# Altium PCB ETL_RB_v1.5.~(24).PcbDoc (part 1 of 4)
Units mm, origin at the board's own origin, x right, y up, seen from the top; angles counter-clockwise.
Board outline 130.3 x 56.5 mm, 8 copper layers (Top Layer, plane 1, M1, plane 2, plane 3, M2, plane 4, Bottom Layer), stack 0.972 mm thick; 212 components, 186 nets, 1961 pads, 978 vias.
Unrouted connection lines stored in the file: 395.
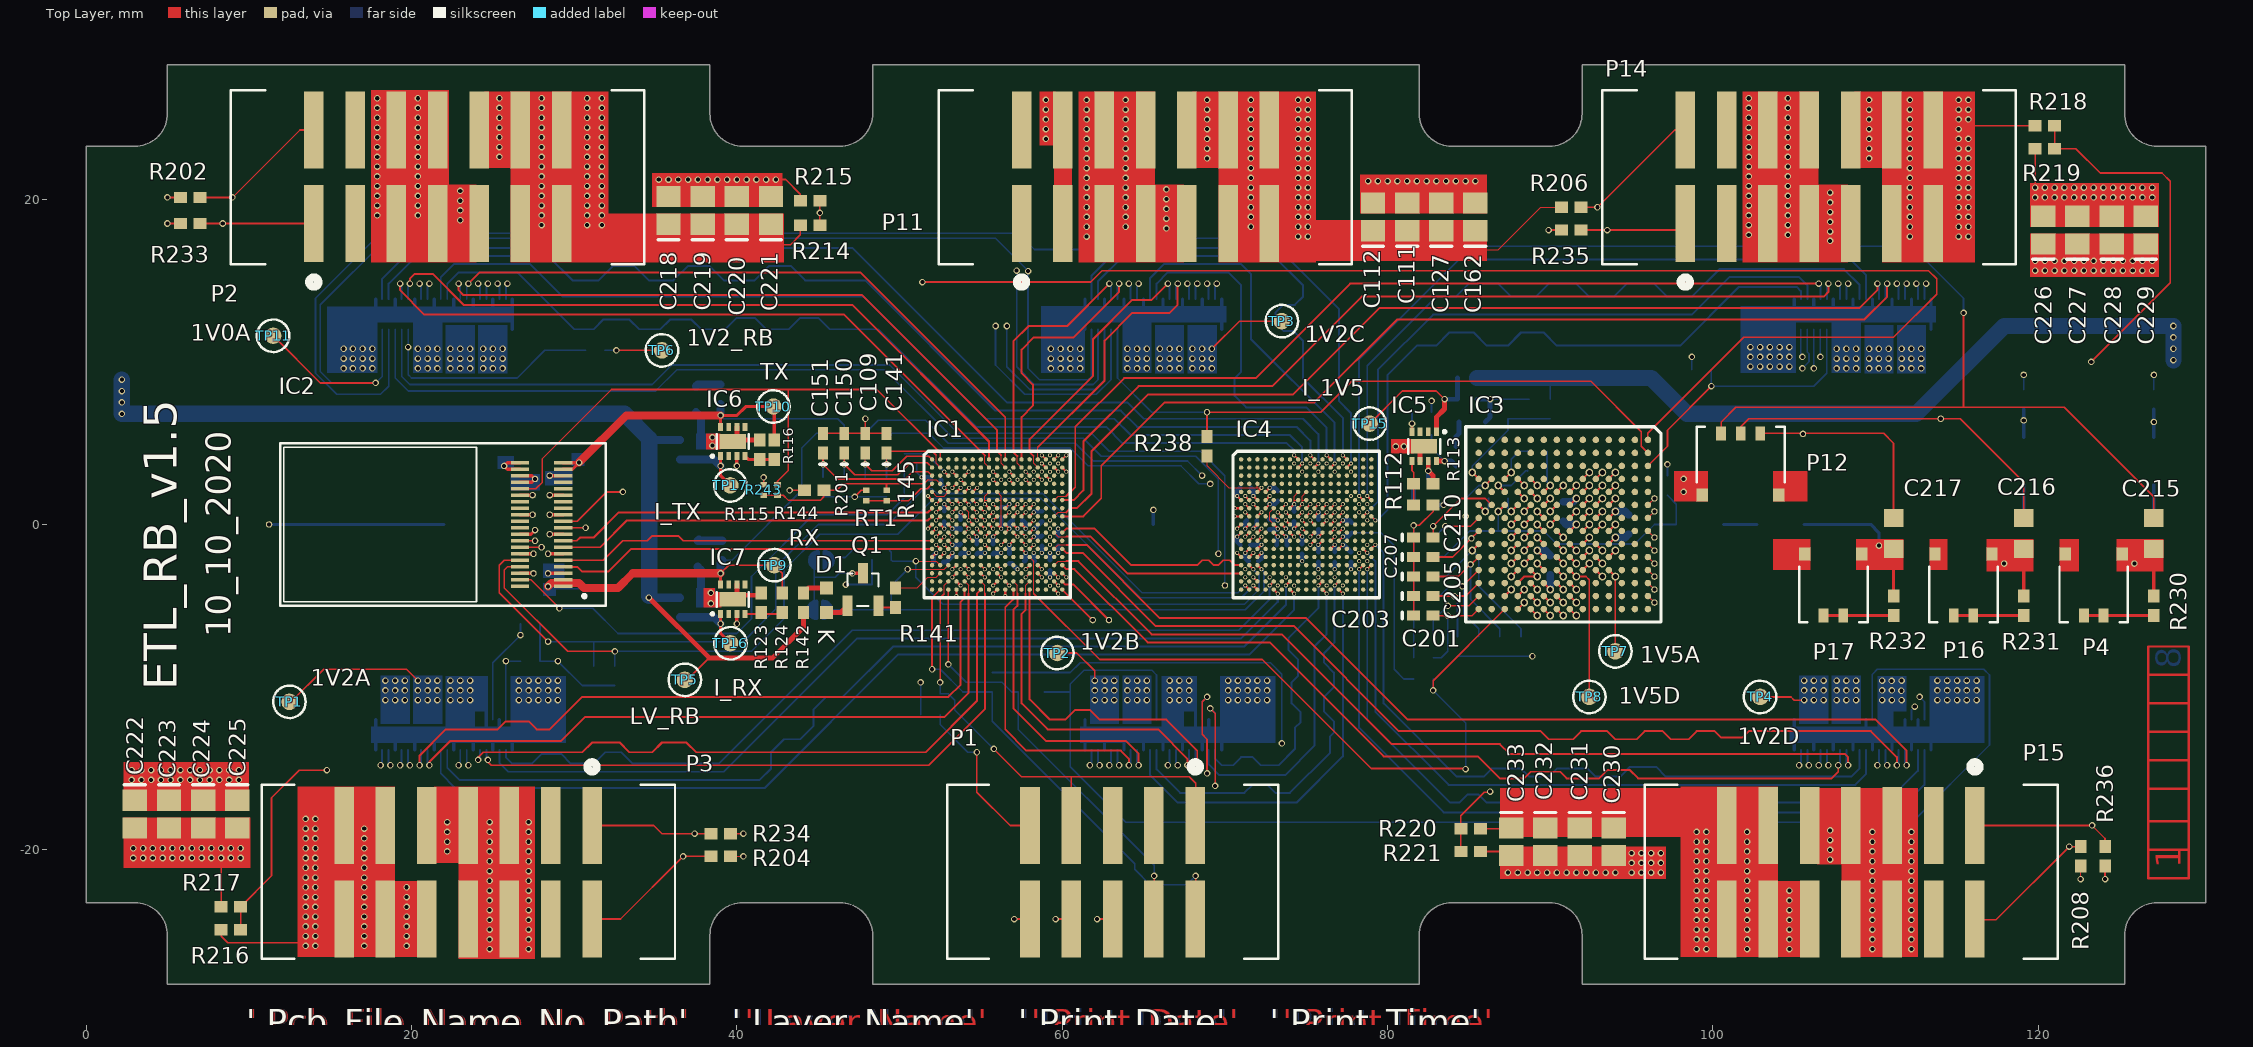
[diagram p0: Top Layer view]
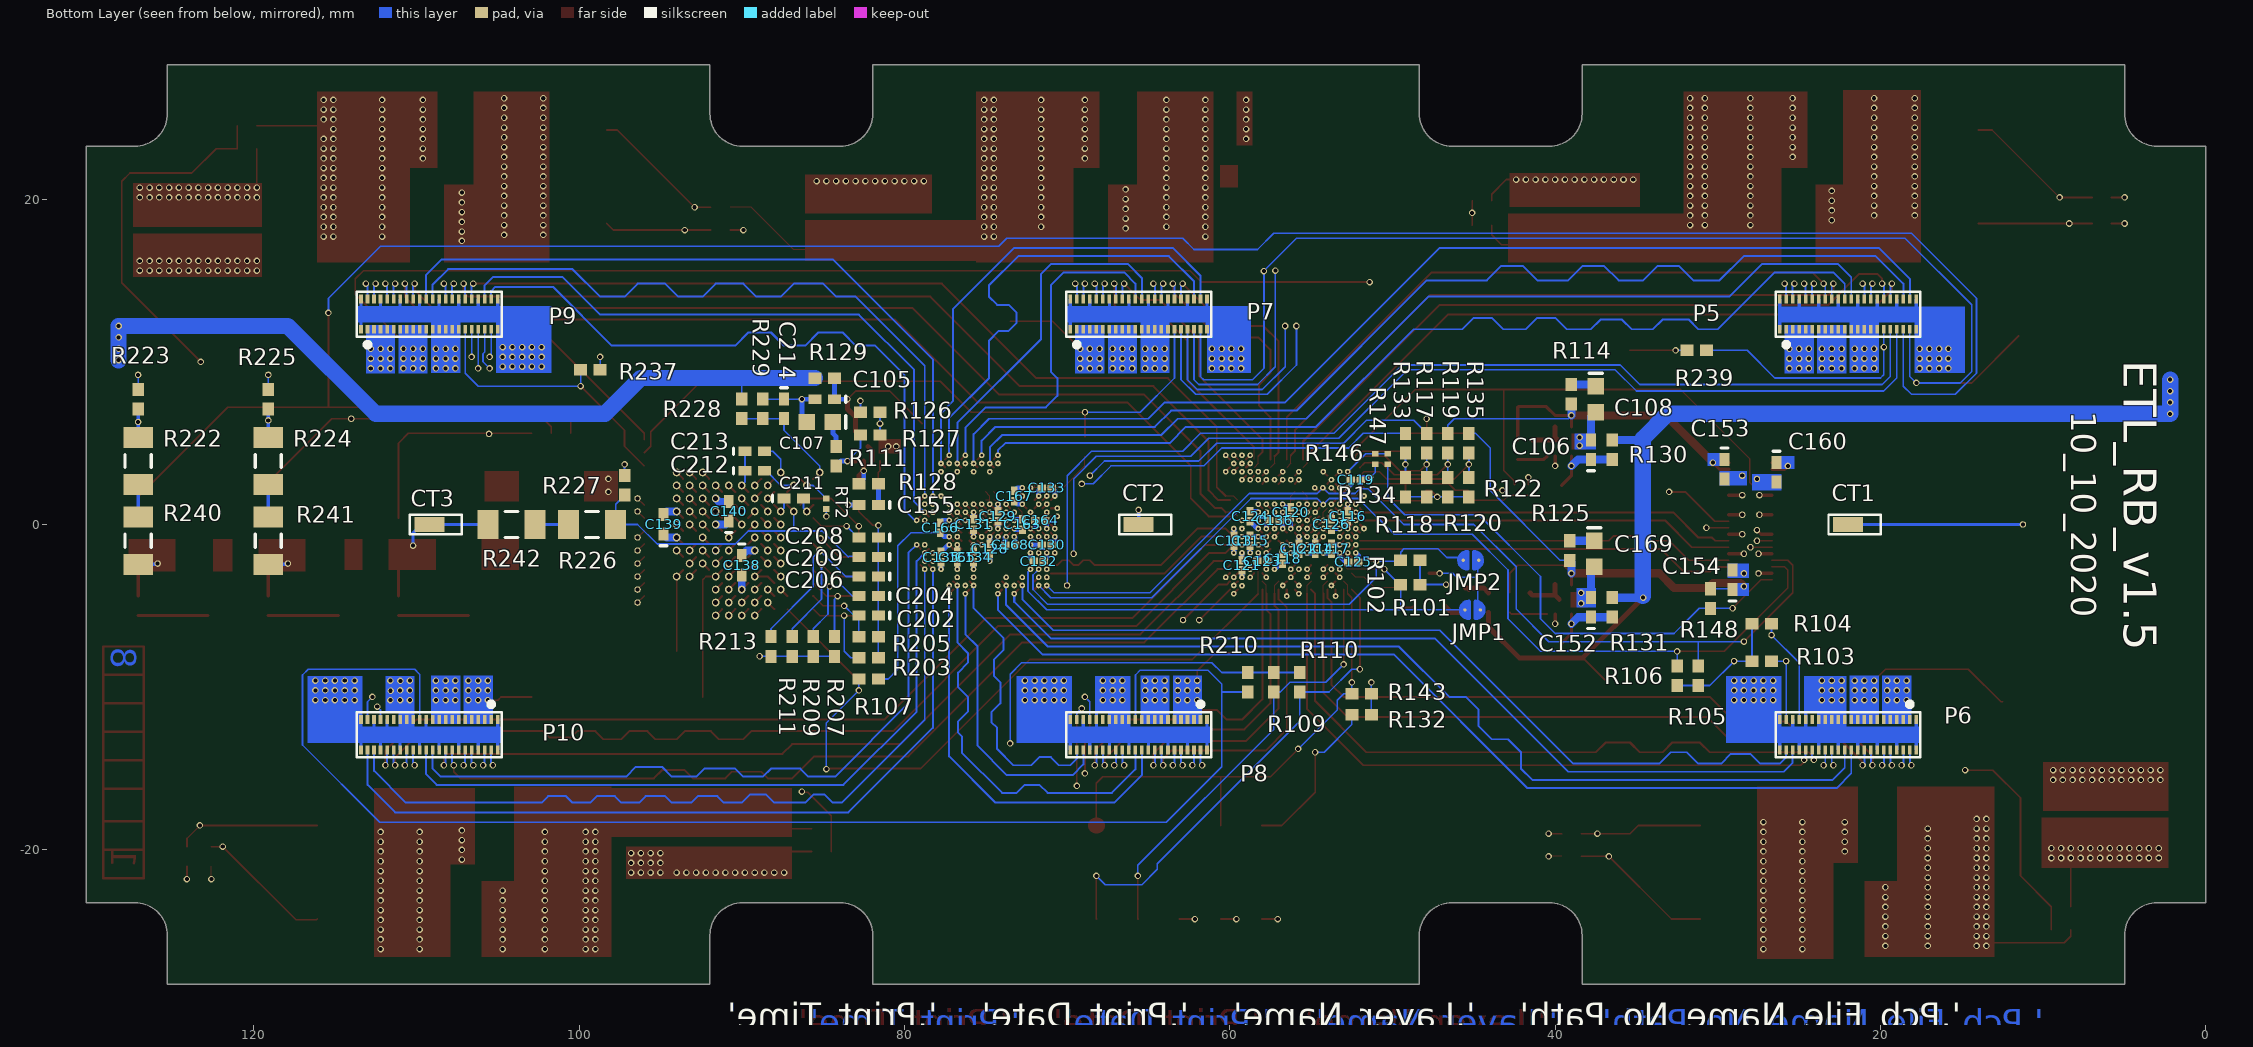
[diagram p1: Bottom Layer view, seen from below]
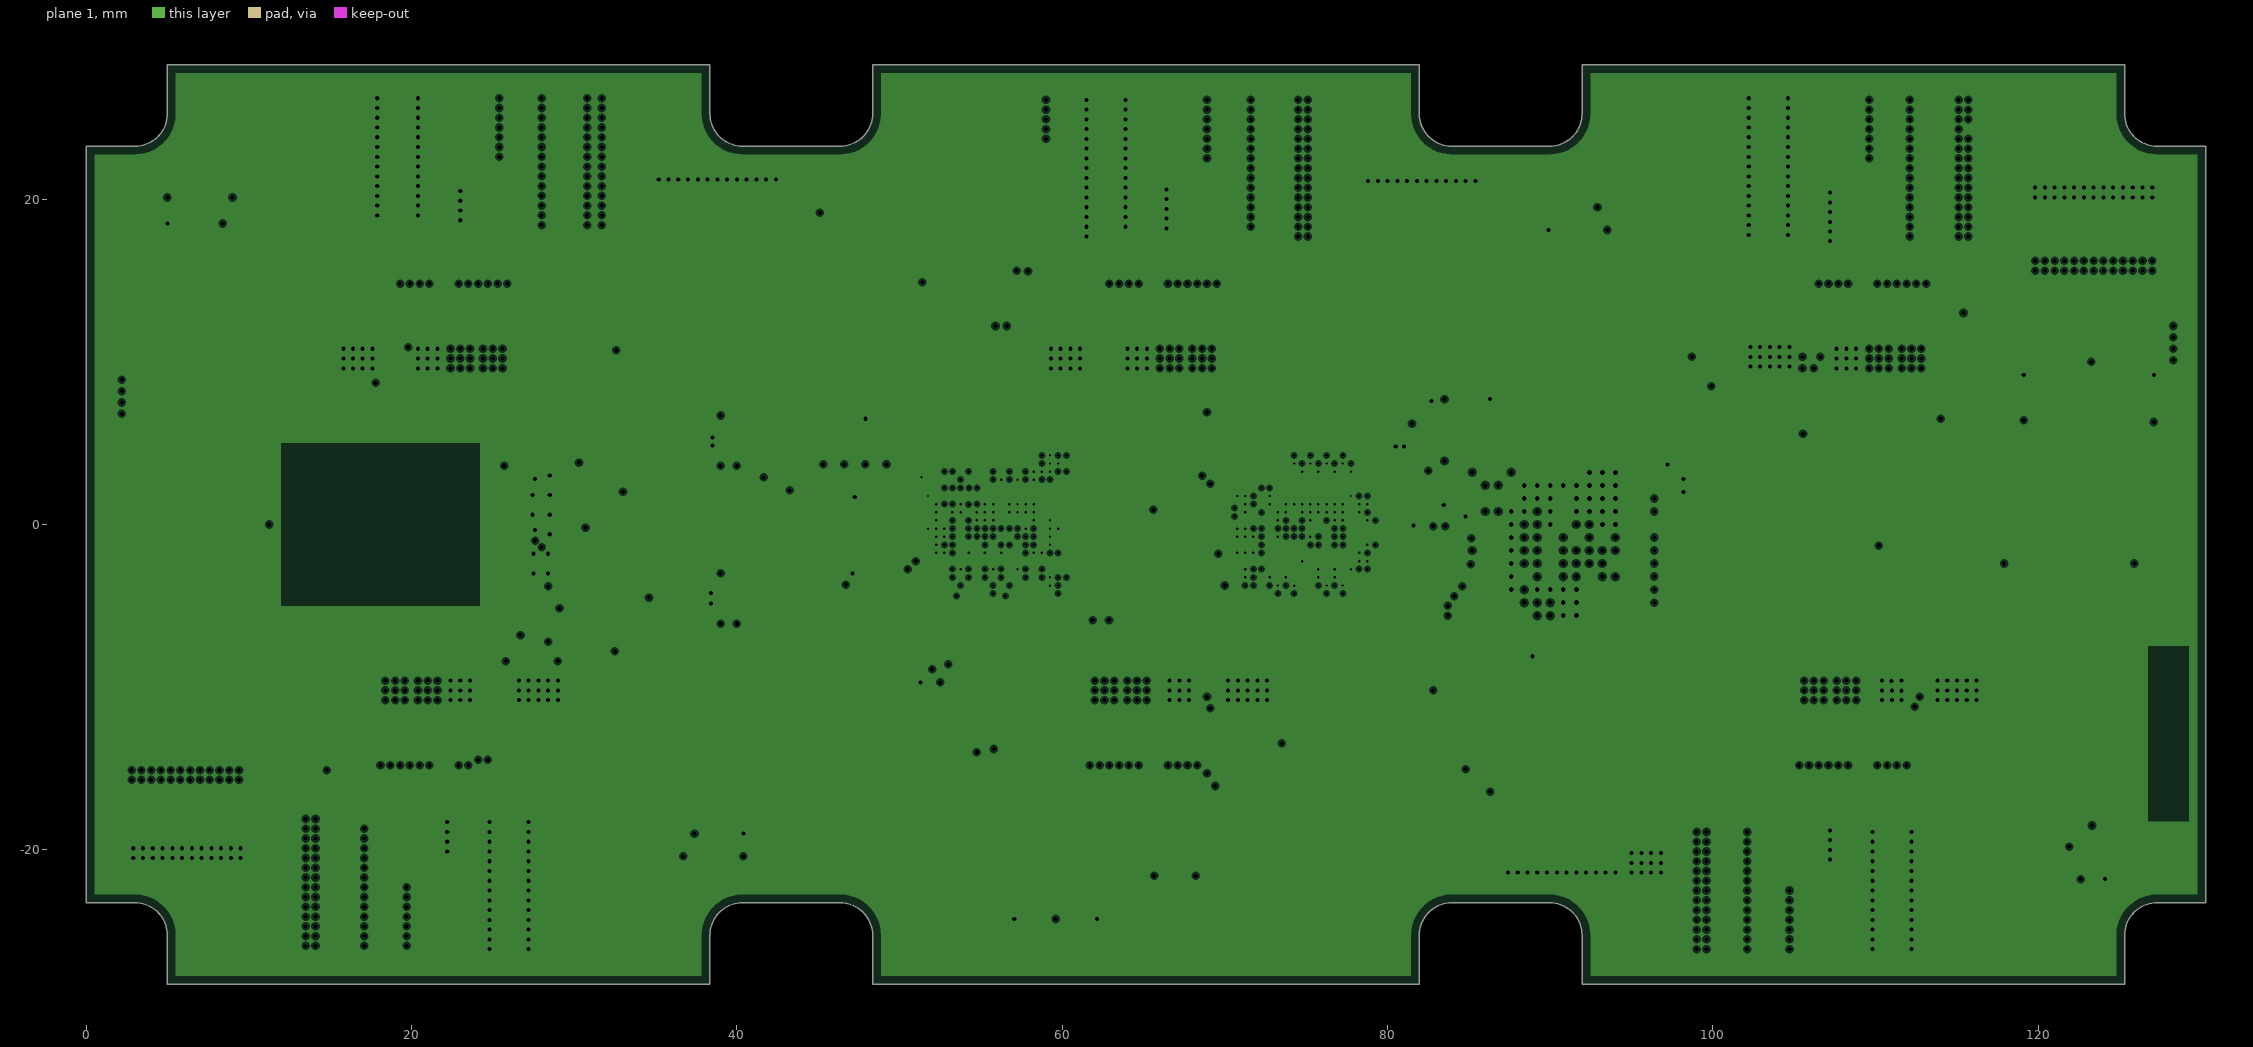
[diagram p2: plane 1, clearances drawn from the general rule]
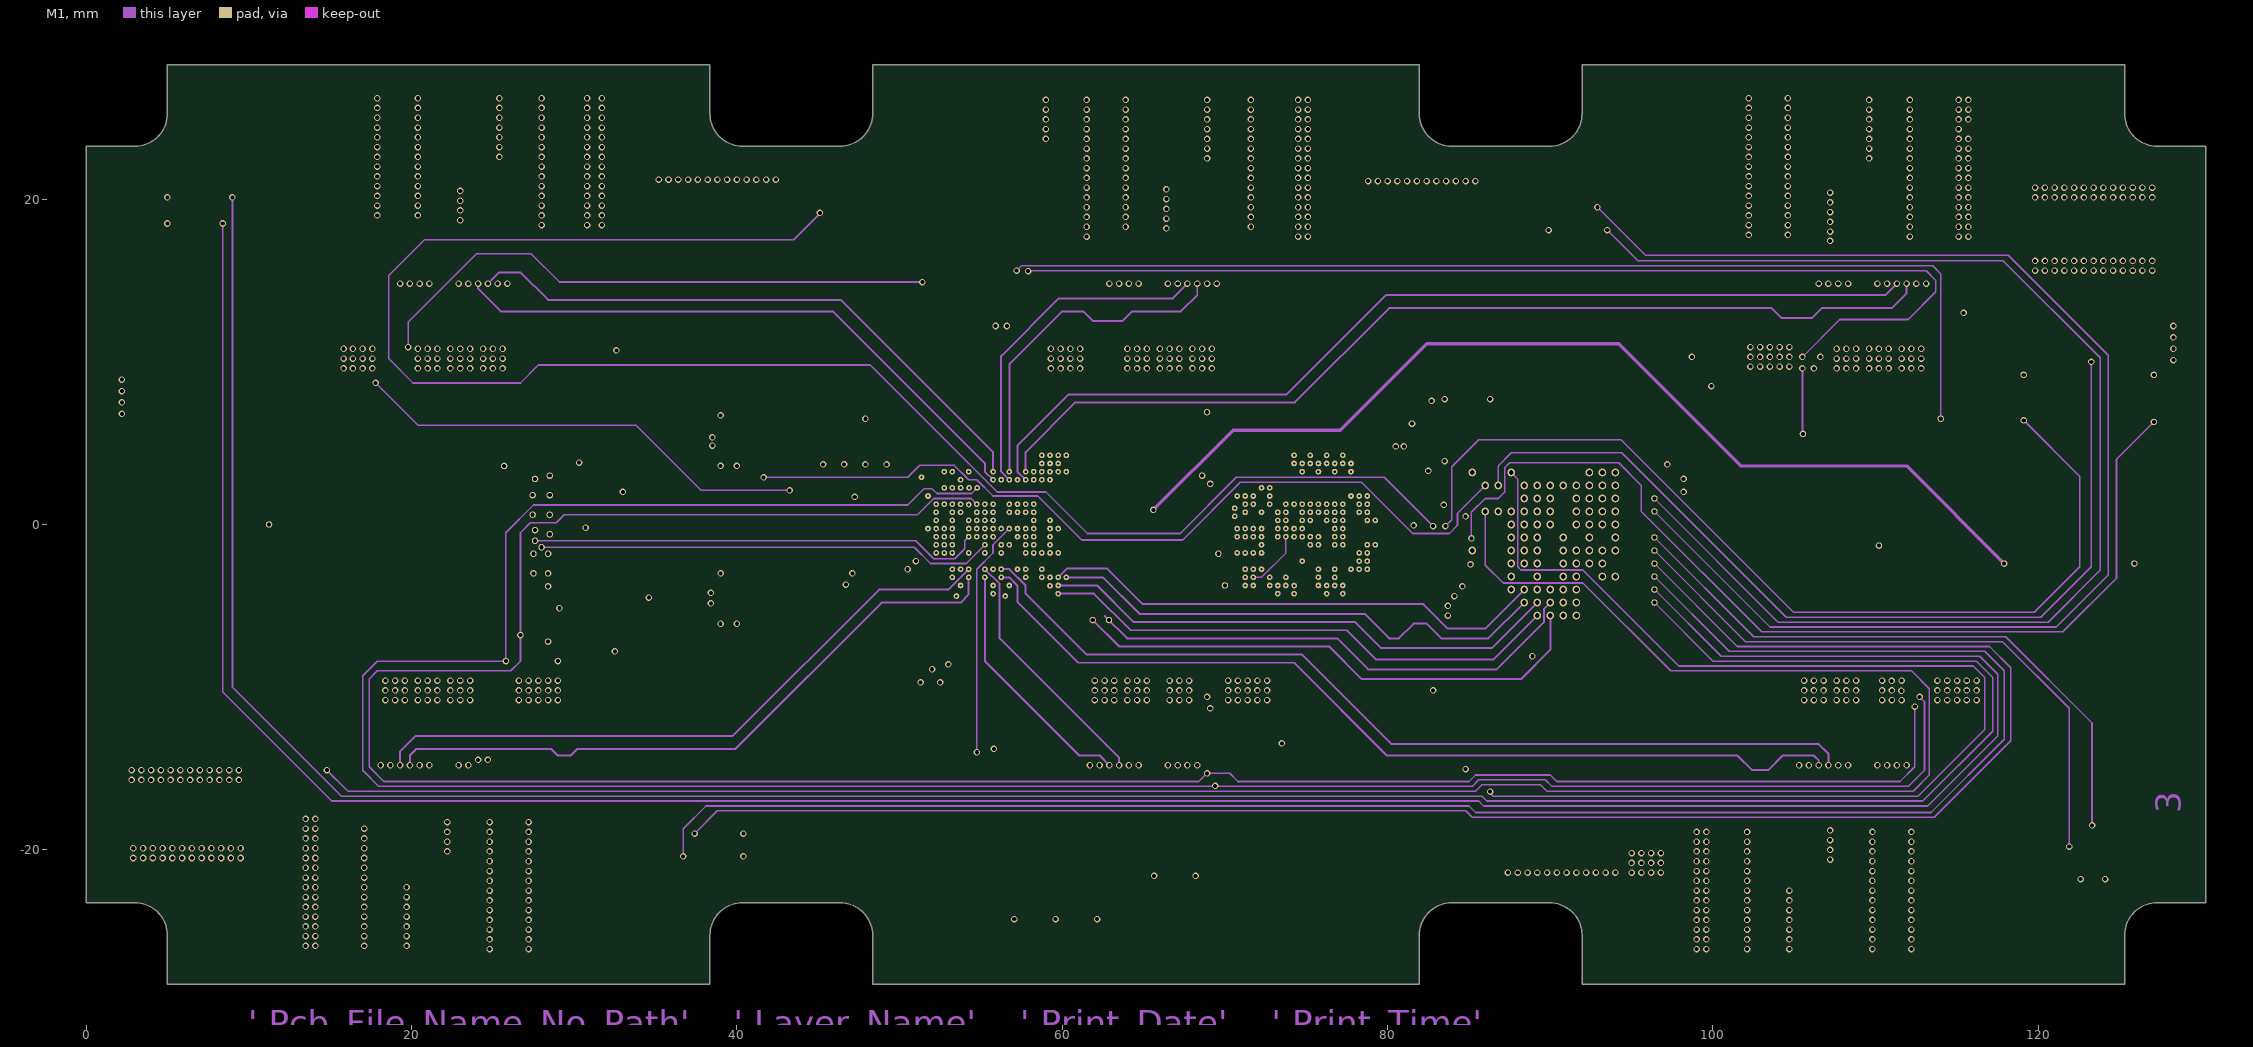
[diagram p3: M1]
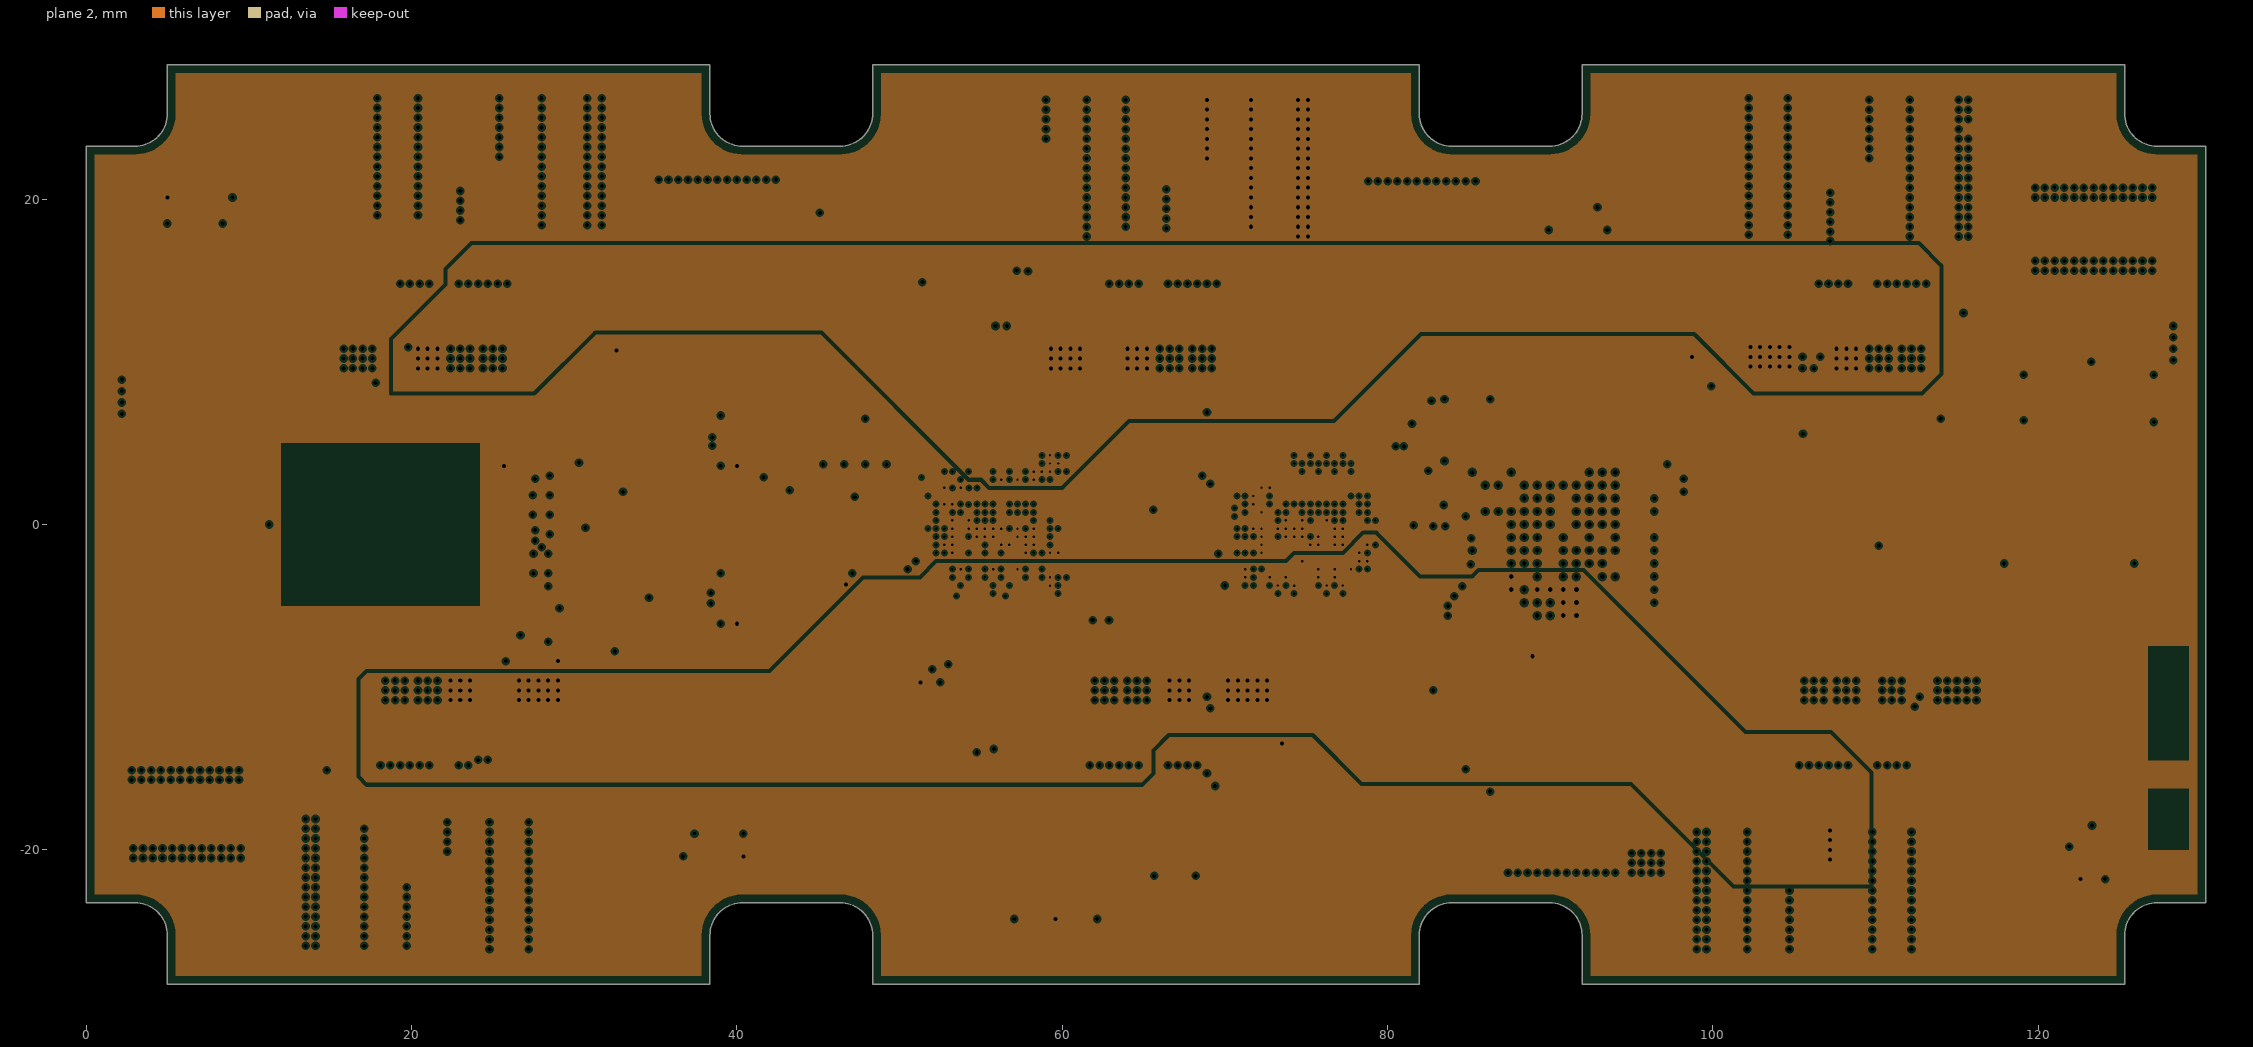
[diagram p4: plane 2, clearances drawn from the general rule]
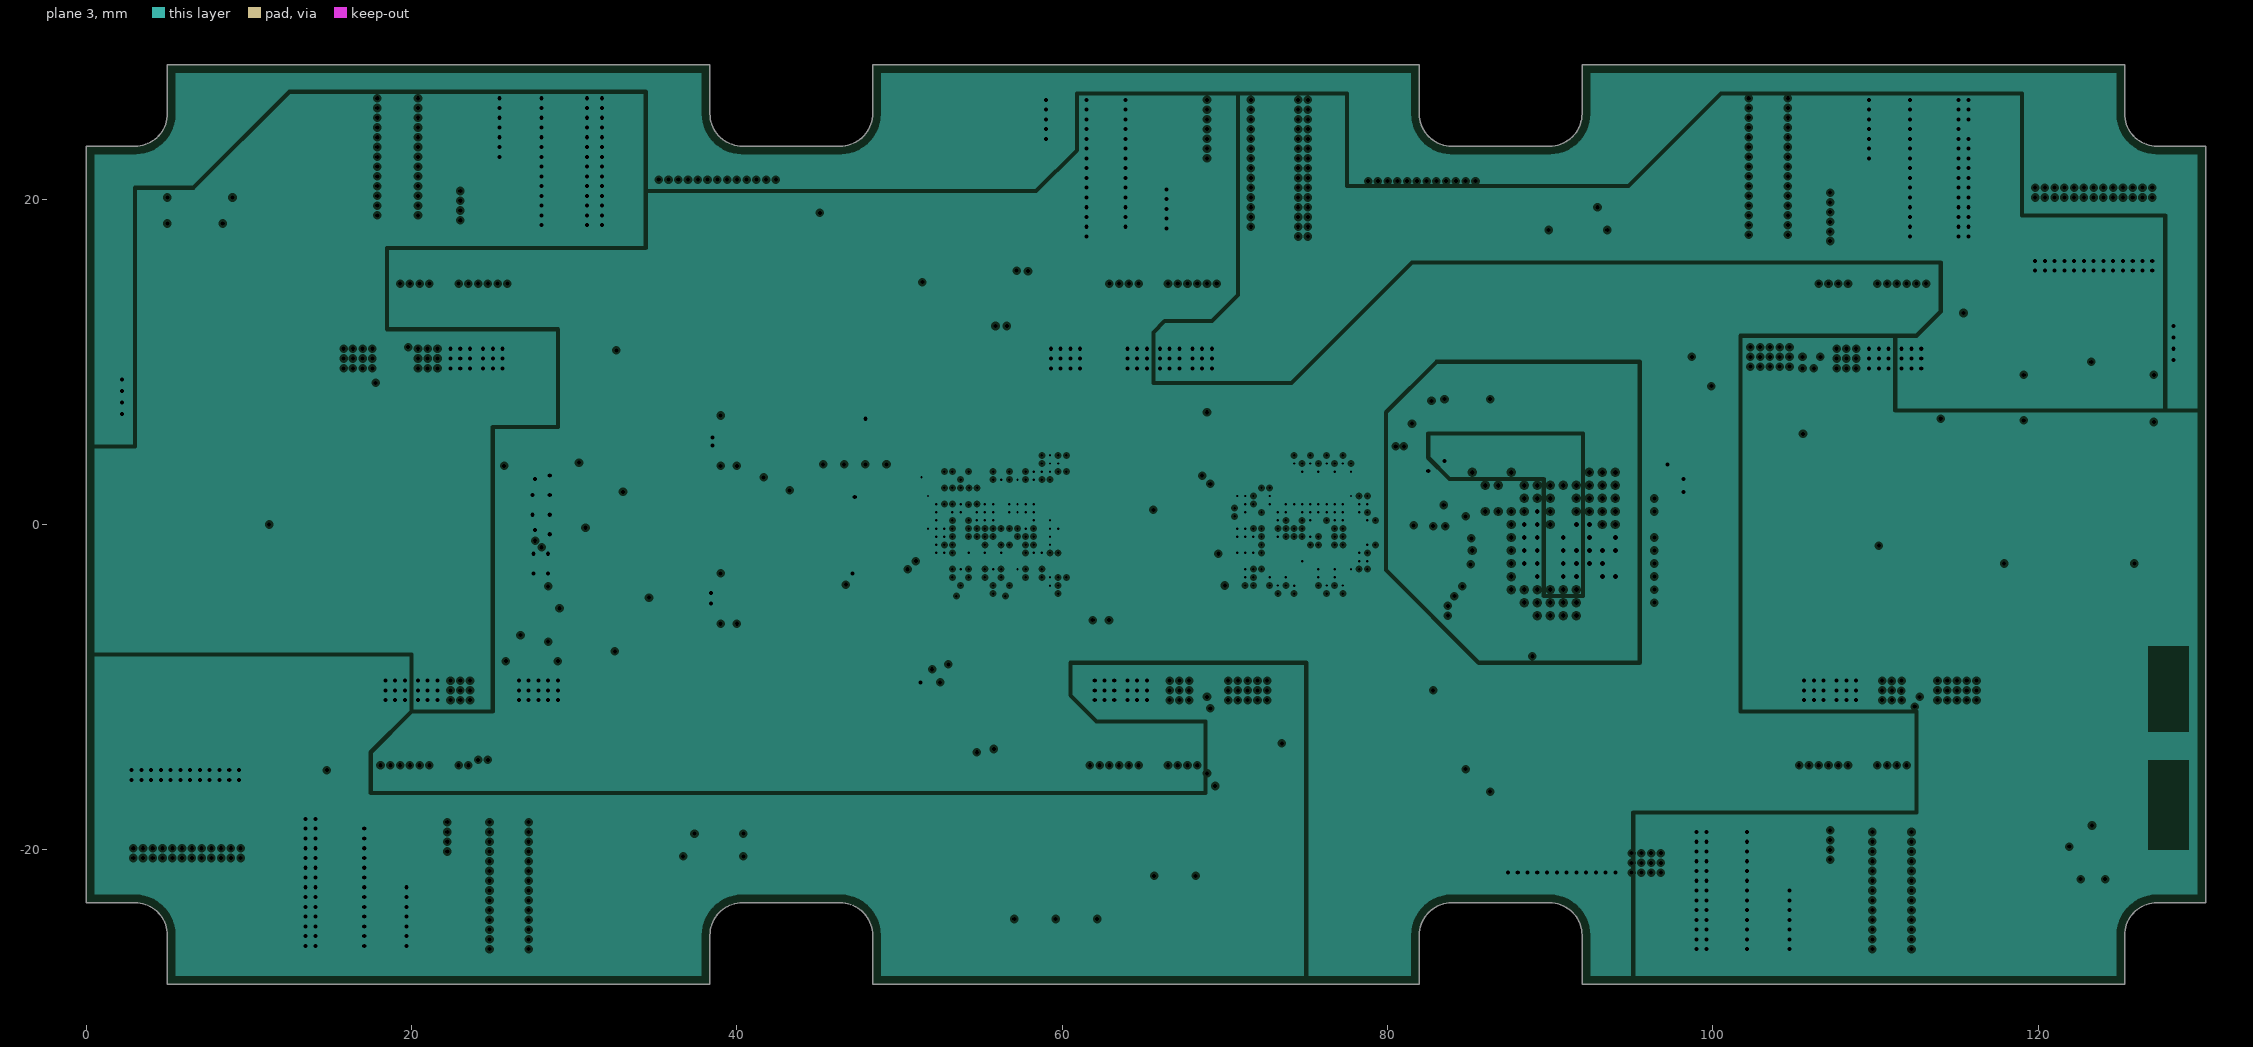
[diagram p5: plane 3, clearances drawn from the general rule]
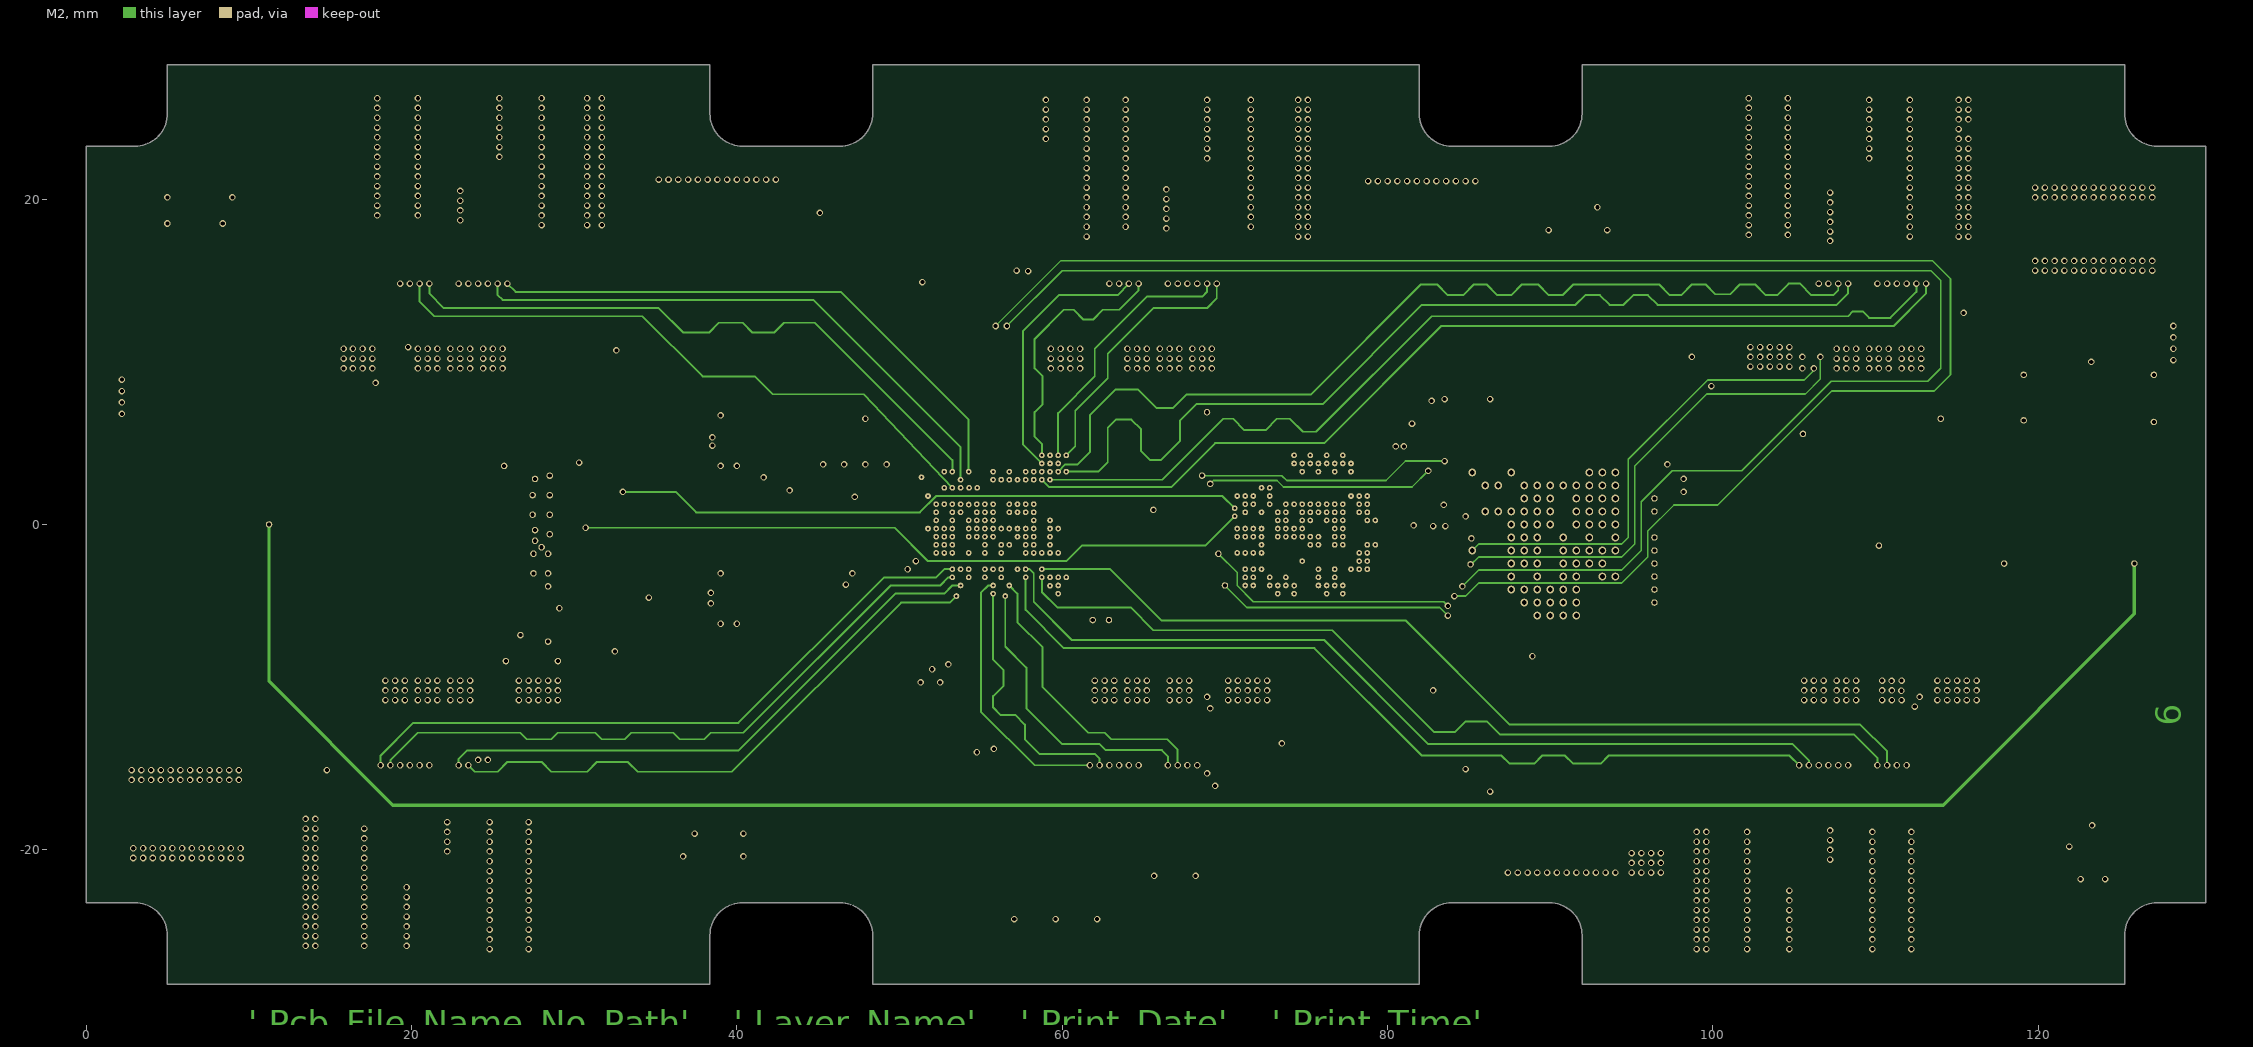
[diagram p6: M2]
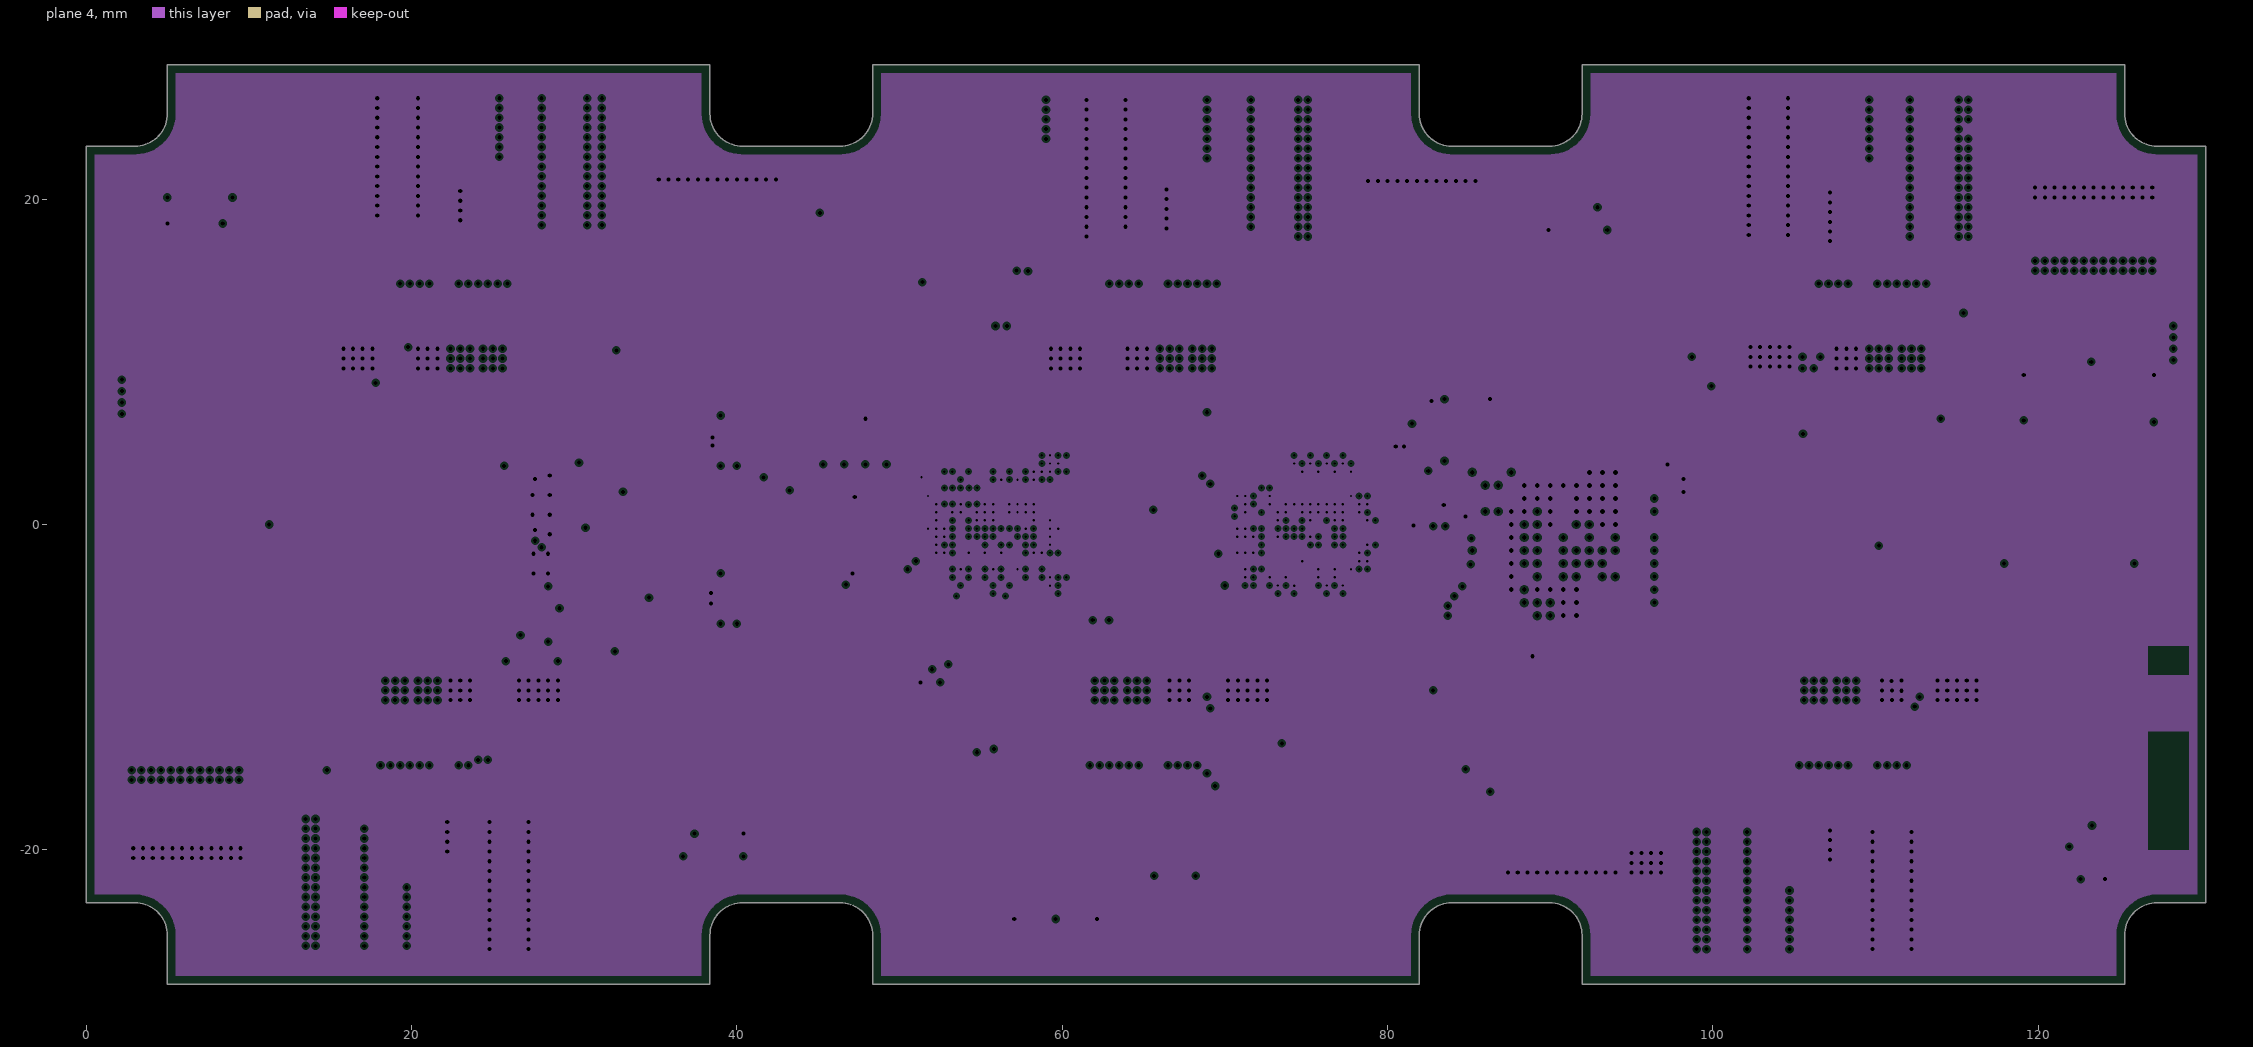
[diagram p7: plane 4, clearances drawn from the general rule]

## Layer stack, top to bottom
Top Solder: solder mask 0.0178, Solder Resist, Dk 4.1
Top Layer: signal copper 0.035
Dielectric 1: prepreg 0.0691, 1080, Dk 3.4
plane 1: plane copper 0.035, net GND
Dielectric 2: core 0.1016, TU-863, Dk 3.7
M1: signal copper 0.018
Dielectric 3: prepreg 0.1417, 1080, Dk 3.4
plane 2: plane copper 0.035, net (Multiple Nets)
Dielectric 4: core 0.1016, TU-863, Dk 3.7
plane 3: plane copper 0.035, net (Multiple Nets)
Dielectric 5: prepreg 0.1417, 1080, Dk 3.4
M2: signal copper 0.018
Dielectric 6: core 0.1016, TU-863, Dk 3.7
plane 4: plane copper 0.035, net GND
Dielectric 7: prepreg 0.0691, 1080, Dk 3.4
Bottom Layer: signal copper 0.035
Bottom Solder: solder mask 0.0178, Solder Resist, Dk 4.1

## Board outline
5,-28.25 5,-25.25 ccw(c3,-25.25) 3,-23.25 0,-23.25 0,23.25 3,23.25 ccw(c3,25.25) 5,25.25 5,28.25 38.35,28.25 38.35,25.25 ccw(c40.35,25.25) 40.35,23.25 46.35,23.25 ccw(c46.35,25.25) 48.35,25.25 48.35,28.25 81.95,28.25 81.95,25.25 ccw(c83.95,25.25) 83.95,23.25 89.95,23.25 ccw(c89.95,25.25) 91.95,25.25 91.95,28.25 125.3,28.25 125.3,25.25 ccw(c127.3,25.25) 127.3,23.25 130.3,23.25 130.3,-23.25 127.3,-23.25 ccw(c127.3,-25.25) 125.3,-25.25 125.3,-28.25 91.95,-28.25 91.95,-25.25 ccw(c89.95,-25.25) 89.95,-23.25 83.95,-23.25 ccw(c83.95,-25.25) 81.95,-25.25 81.95,-28.25 48.35,-28.25 48.35,-25.25 ccw(c46.35,-25.25) 46.35,-23.25 40.35,-23.25 ccw(c40.35,-25.25) 38.35,-25.25 38.35,-28.25

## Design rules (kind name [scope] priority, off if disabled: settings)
Clearance [All] p1: gap=0.076 ignorepadtopadclearanceinfootprint=FALSE except(0: Arc-Hole Track-Hole SMDPad-Hole THPad-Hole Via-Hole Fill-Hole Poly-Hole Region-Hole Text-Hole)
Height [All] p1 off: minheight=0 maxheight=25.4 prefheight=12.7
HoleToHoleClearance HoleToHoleClearance_1 [InNet('GND') or InNet('LV_RB') or InNet('1V5A') or InNet('1V5D') or InNet('1V2A') or InNet('1V2B') or InNet('1V2C') or InNet('1V2D') vs InNet('GND') or InNet('LV_RB') or InNet('1V5A') or InNet('1V5D') or InNet('1V2A') or InNet('1V2B') or InNet('1V2C') or InNet('1V2D')] p1: gap=0.15 allowstackedmicrovias=TRUE
HoleToHoleClearance [All] p2: gap=0.254 allowstackedmicrovias=TRUE
MinimumSolderMaskSliver [All] p1: minsoldermaskwidth=0.025
PlaneClearance PlaneClearance_1 [InNetClass('BV')] p1: clearance=0.508
PlaneClearance [All] p2: clearance=0.14
PlaneConnect PlaneConnect_1 [All] p1: planeconnectstyle=Direct reliefexpansion=0.508 reliefentries=4 reliefconductorwidth=0.254 reliefairgap=0.254
PolygonConnect [All] p1: connectstyle=Relief reliefconductorwidth=0.254 reliefentries=4 polygonreliefangle="90 Angle" airgapwidth=0.254
RoomDefinition WP7B [InComponentClass('WP7B')] p1 off: confinementstyle=ConfineIn formatcopy=TRUE lockcomponents=FALSE outline 192.75,16.8 613.75,16.8 613.75,46.8 192.75,46.8
RoomDefinition lpGBT [InComponentClass('lpGBT')] p2 off: confinementstyle=ConfineIn formatcopy=TRUE lockcomponents=FALSE outline 192,-36.75 1047,-36.75 1047,-1.75 192,-1.75
RoutingVias [All] p1: holewidth=0.25 width=0.4 viastyle="Through Hole" minholewidth=0.15 minwidth=0.25 maxholewidth=0.711 maxwidth=1.27
SilkToSilkClearance [All] p1: silktosilkclearance=0.025
SilkToSolderMaskClearance [IsPad] p1: minsilkscreentomaskgap=0.025 clearancetoexposedcopper=TRUE
SolderMaskExpansion [All] p1: expansion=0.051 istentingtop=FALSE
Width Width_HS [InNetClass('HS')] p1: maxlimit=0.13 minlimit=0.076 preferedwidth=0.12 midlayer1_minwidth=0.12 midlayer1_maxwidth=0.12 midlayer2_minwidth=0.12 midlayer2_maxwidth=0.12 bottomlayer_minwidth=0.12 bottomlayer_maxwidth=0.12 minimp=50.000000 maximp=50.000000 favimp=50.000000 // impedance controlled signals
Width [All] p2: maxlimit=2.54 minlimit=0.076 preferedwidth=0.12 toplayer_minwidth=0.076 midlayer1_minwidth=0.076 minimp=50.000000 maximp=50.000000 favimp=50.000000
23 further rules are at their usual default settings.

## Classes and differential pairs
component class WP7B: C201 C202 C203 C204 C205 C206 C207 C208 C209 C210 C211 C212 C213 C214 C215 C216 C217 C218 C219 C220 C221 C222 C223 C224 C225 C226 C227 C228 C229 C230 C231 C232 C233 CT1 CT2 CT3 P2 P3 P4 P5 P6 P7 P8 P9 P10 P12 P14 P15 P16 P17 R201 R202 R203 R204 R205 R206 R207 R208 R209 R210 R211 R213 R214 R215 R216 R217 R218 R219 R220 R221 R222 R223 R224 R225 R226 R227 R228 R229 R230 R231 R232 R233 R234 R235 R236 R237 R238 R239 R240 R241 R242 R243 RT2 TP1 TP2 TP3 TP4 TP5 TP6 TP7 TP8 TP9 TP10 TP11
component class lpGBT: C105 C106 C107 C108 C109 C111 C112 C113 C114 C115 C116 C117 C118 C119 C120 C121 C122 C123 C124 C125 C126 C127 C128 C129 C130 C131 C132 C133 C134 C135 C136 C138 C139 C140 C141 C150 C151 C152 C153 C154 C155 C160 C162 C163 C164 C165 C166 C167 C168 C169 D1 IC1 IC2 IC3 IC4 IC5 IC6 IC7 JMP1 JMP2 P1 P11 Q1 R101 R102 R103 R104 R105 R106 R107 R109 R110 R111 R112 R113 R114 R115 R116 R117 R118 R119 R120 R122 R123 R124 R125 R126 R127 R128 R129 R130 R131 R132 R133 R134 R135 R141 R142 R143 R144 R145 R146 R147 R148 RT1 TP15 TP16 TP17

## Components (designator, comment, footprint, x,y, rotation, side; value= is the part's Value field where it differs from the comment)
C105 "GRM155R71E104ME14D" capc1005n 84.9,7.7 r0 bottom value=0.1uF
C106 "GRM155R71E104ME14D" capc1005n 37.8,4.6 r90 bottom value=0.1uF
C107 "GRM185R60J106ME15J" CAPC1608N 85.2,6.3 r0 bottom value=10uF
C108 "GRM185R60J106ME15J" CAPC1608N 37.5,7.7 r270 bottom value=10uF
C109 "GRM155R71E104ME14D" capc1005n 47.9,5 r90 top value=0.1uF
C111 "GRM188R60J476ME15D" capc2012n 81.2,18.9 r90 top value=47uF
C112 "GRM188R60J476ME15D" capc2012n 79.1,18.9 r90 top value=47uF
C113 "GRM033R61C104KE84D" CAPC0603N 59.75,-1 r90 bottom value=0.1uF
C114 "GRM033R61C104KE84D" CAPC0603N 54.75,-1.5 r270 bottom value=0.1uF
C115 "GRM033R61C104KE84D" CAPC0603N 58.75,-1 r270 bottom value=0.1uF
C116 "GRM033R61C104KE84D" CAPC0603N 52.75,0.5 r270 bottom value=0.1uF
C117 "GRM033R61C104KE84D" CAPC0603N 53.75,-1.5 r270 bottom value=0.1uF
C118 "GRM033R61C104KE84D" CAPC0603N 56.75,-2.1 r270 bottom value=0.1uF
C119 "GRM033R61C104KE84D" CAPC0603N 52.25,2.75 r180 bottom value=0.1uF
C120 "GRM033R61C104KE84D" CAPC0603N 56.25,0.75 r90 bottom value=0.1uF
C121 "GRM033R61C104KE84D" CAPC0603N 59.25,-2.5 r270 bottom value=0.1uF
C122 "GRM033R61C153KE84D" CAPC0603N 55.75,-1.5 r270 bottom value=15nF
C123 "GRM033R61C153KE84D" CAPC0603N 58,-2.25 r0 bottom value=15nF
C124 "GRM033R61C153KE84D" CAPC0603N 58.75,0.5 r90 bottom value=15nF
C125 "GRM033R61C153KE84D" CAPC0603N 52.4,-2.3 r180 bottom value=15nF
C126 "GRM033R61C153KE84D" CAPC0603N 53.75,0 r90 bottom value=15nF
C127 "GRM188R60J476ME15D" capc2012n 83.3,18.9 r90 top value=47uF
C128 "GRM033R61C104KE84D" CAPC0603N 74.75,-1.5 r270 bottom value=0.1uF
C129 "GRM033R61C104KE84D" CAPC0603N 74.25,0.5 r90 bottom value=0.1uF
C130 "GRM033R61C104KE84D" CAPC0603N 71.25,-1.25 r180 bottom value=0.1uF
C131 "GRM033R61C104KE84D" CAPC0603N 75.75,0 r90 bottom value=0.1uF
C132 "GRM033R61C104KE84D" CAPC0603N 71.75,-2.25 r180 bottom value=0.1uF
C133 "GRM033R61C104KE84D" CAPC0603N 71.25,2.25 r180 bottom value=0.1uF
C134 "GRM033R61C104KE84D" CAPC0603N 75.75,-2 r270 bottom value=0.1uF
C135 "GRM033R61C104KE84D" CAPC0603N 77.75,-2 r270 bottom value=0.1uF
C136 "GRM033R61C104KE84D" CAPC0603N 57.25,0.25 r0 bottom value=0.1uF
C138 "GRM155R71E104ME14D" capc1005n 90,-2.5 r270 bottom value=0.1uF
C139 "GRM155R71E104ME14D" capc1005n 94.8,0 r90 bottom value=0.1uF
C140 "GRM155R71E104ME14D" capc1005n 90.8,0.8 r90 bottom value=0.1uF
C141 "GRM155R71E104ME14D" capc1005n 49.2,5 r90 top value=0.1uF
C150 "GRM155R71E104ME14D" capc1005n 46.6,5 r90 top value=0.1uF
C151 "GRM155R71E104ME14D" capc1005n 45.3,5 r90 top value=0.1uF
C152 "GRM155R71E104ME14D" capc1005n 37.8,-5.1 r90 bottom value=0.1uF
C153 "GRM155R71E104ME14D" capc1005n 29.6,3.4 r270 bottom value=0.1uF
C154 "GRM155R71E104ME14D" capc1005n 29.1,-3.4 r90 bottom value=0.1uF
C155 "GRM153R60J475ME15D" capc1005n 82.2,1.2 r0 bottom value=4.7uF
C160 "GRM155R71E104ME14D" CAPC1005N 26.4,3.2 r270 bottom value=0.1uF
C162 "GRM188R60J476ME15D" capc2012n 85.4,18.9 r90 top value=47uF
C163 "GRM033R61C104KE84D" CAPC0603N 72.75,0 r90 bottom value=0.1uF
C164 "GRM033R61C153KE84D" CAPC0603N 71.65,0.25 r180 bottom value=15nF
C165 "GRM033R61C153KE84D" CAPC0603N 76.75,-2 r270 bottom value=15nF
C166 "GRM033R61C153KE84D" CAPC0603N 77.8,-0.2 r90 bottom value=15nF
C167 "GRM033R61C153KE84D" CAPC0603N 73.25,1.75 r270 bottom value=15nF
C168 "GRM033R61C153KE84D" CAPC0603N 73.5,-1.25 r180 bottom value=15nF
C169 "GRM185R60J106ME15J" CAPC1608N 37.6,-1.8 r270 bottom value=10uF
C201 "GRM155R71E104ME14D" capc1005n 82.2,-5.6 r0 top value=0.1uF
C202 "GRM155R71E104ME14D" capc1005n 82.2,-5.6 r0 bottom value=0.1uF
C203 "GRM155R71E104ME14D" capc1005n 82.2,-4.4 r0 top value=0.1uF
C204 "GRM155R71E104ME14D" capc1005n 82.2,-4.4 r0 bottom value=0.1uF
C205 "GRM155R71E104ME14D" capc1005n 82.2,-3.2 r0 top value=0.1uF
C206 "GRM155R71E104ME14D" capc1005n 82.2,-3.2 r0 bottom value=0.1uF
C207 "GRM155R71E104ME14D" capc1005n 82.2,-2 r0 top value=0.1uF
C208 "GRM155R71E104ME14D" capc1005n 82.2,-0.8 r0 bottom value=0.1uF
C209 "GRM155R71E104ME14D" capc1005n 82.2,-2 r0 bottom value=0.1uF
C210 "GRM155R71E104ME14D" capc1005n 82.2,-0.8 r0 top value=0.1uF
C211 "GRM155R71E104ME14D" capc1005n 86.8,1.6 r180 bottom value=0.1uF
C212 "GRM155R71E104ME14D" capc1005n 89.2,3.3 r180 bottom value=0.1uF
C213 "GRM155R71E104ME14D" capc1005n 89.2,4.5 r180 bottom value=0.1uF
C214 "GRM155R71E104ME14D" capc1005n 87.4,7.1 r270 bottom value=0.1uF
C215 "C0805X7R102-152MNE" VENKEL0805 127.1,-1.5 r90 top value=1500pF
C216 "C0805X7R102-152MNE" VENKEL0805 119.1,-1.5 r90 top value=1500pF
C217 "C0805X7R102-152MNE" VENKEL0805 111.1,-1.5 r90 top value=1500pF
C218 "GRM188R60J476ME15D" capc2012n 35.8,19.3 r90 top value=47uF
C219 "GRM188R60J476ME15D" capc2012n 37.9,19.3 r90 top value=47uF
C220 "GRM188R60J476ME15D" capc2012n 40,19.3 r90 top value=47uF
C221 "GRM188R60J476ME15D" capc2012n 42.1,19.3 r90 top value=47uF
C222 "GRM188R60J476ME15D" capc2012n 3,-17.8 r270 top value=47uF
C223 "GRM188R60J476ME15D" capc2012n 5.1,-17.8 r270 top value=47uF
C224 "GRM188R60J476ME15D" capc2012n 7.2,-17.8 r270 top value=47uF
C225 "GRM188R60J476ME15D" capc2012n 9.3,-17.8 r270 top value=47uF
C226 "GRM188R60J476ME15D" capc2012n 120.3,18.1 r90 top value=47uF
C227 "GRM188R60J476ME15D" capc2012n 122.4,18.1 r90 top value=47uF
C228 "GRM188R60J476ME15D" capc2012n 124.5,18.1 r90 top value=47uF
C229 "GRM188R60J476ME15D" capc2012n 126.6,18.1 r90 top value=47uF
C230 "GRM188R60J476ME15D" capc2012n 93.9,-19.5 r270 top value=47uF
C231 "GRM188R60J476ME15D" capc2012n 91.8,-19.5 r270 top value=47uF
C232 "GRM188R60J476ME15D" capc2012n 89.7,-19.5 r270 top value=47uF
C233 "GRM188R60J476ME15D" capc2012n 87.6,-19.5 r270 top value=47uF
CT1 "TE1551631-5" CONTACT 22,0 r0 bottom locked
CT2 "TE1551631-5" CONTACT 65.6,0 r0 bottom locked
CT3 "TE1551631-5" CONTACT 109.2,0 r0 bottom locked
D1 "LTST-C191KGKT" LED_RED 45.5,-3.9 r270 top
IC1 "LPGBT" BGA289X17 52,4 r0 top
IC2 "DF40C-40DS-0.4V" VTRX+ 29.33,-3.8 r90 top locked
IC3 "GBT-SCA" BGA196C80P14X14_1200X1200X170 96,5.2 r270 top
IC4 "LPGBT" BGA289X17 71,4 r0 top
IC5 "linPOL12V" WDFNX208 83,5.7 r180 top
IC6 "linPOL12V" WDFNX208 39,4.2 r0 top
IC7 "linPOL12V" WDFNX208 39,-5.5 r0 top
JMP1 "Not a component, printed on PCB" JMP2PCB#1 45.1,-5.25 r90 bottom
JMP2 "Not a component, printed on PCB" JMP2PCB#2 45.2,-2.2 r90 bottom
P1 "CnC3020-10-0300-00" cnc10 68.18,-18.5 r180 top
P2 "CnC3020-14-0300-00" cnc14 14,18.5 r0 top locked
P3 "CnC3020-14-0300-00" cnc14 31.1,-18.5 r180 top locked
P4 "DF57-2P-1.2V(21)" DF57-2 122.8,-5.6 r0 top
P5 "WP7B-P040VA1" WP7B-40P 25.8,12 r180 bottom locked
P6 "WP7B-P040VA1" WP7B-40P 18.2,-12 r0 bottom locked
P7 "WP7B-P040VA1" WP7B-40P 69.4,12 r180 bottom locked
P8 "WP7B-P040VA1" WP7B-40P 61.8,-12 r0 bottom locked
P9 "WP7B-P040VA1" WP7B-40P 113,12 r180 bottom locked
P10 "WP7B-P040VA1" WP7B-40P 105.4,-12 r0 bottom locked
P11 "CnC3020-14-0300-00" cnc14 57.5,18.5 r0 top locked
P12 "DF57-3P-1.2V(21)" DF57-3 102.9,5.6 r180 top
P14 "CnC3020-14-0300-00" cnc14 98.3,18.5 r0 top locked
P15 "CnC3020-14-0300-00" cnc14 116.1,-18.5 r180 top locked
P16 "DF57-2P-1.2V(21)" DF57-2 114.8,-5.6 r0 top
P17 "DF57-2P-1.2V(21)" DF57-2 106.8,-5.6 r0 top
Q1 "KSC2223YMTF" SOT-23 46.8,-5 r0 top
R101 "ERJ-2GEJ392X" resc1005n 48.9,-3.7 r180 bottom
R102 "ERJ-2GEJ392X" resc1005n 48.9,-2.2 r0 bottom
R103 "ERJ-2GEJ202X" resc1005n 27.3,-8.4 r0 bottom
R104 "ERJ-2GEJ202X" resc1005n 27.3,-6.1 r0 bottom
R105 "ERJ-2GEJ392X" resc1005n 31.2,-9.3 r270 bottom
R106 "ERJ-2GEJ392X" resc1005n 32.5,-9.3 r270 bottom
R107 "ERJ-2GEJ392X" resc1005n 82.2,-9.5 r0 bottom
R109 "ERJ-2GEJ392X" resc1005n 57.3,-9.7 r90 bottom
R110 "ERJ-2GEJ392X" resc1005n 55.7,-9.7 r90 bottom
R111 "ERJ-2BQJR30X" resc1005n 84.2,4.2 r90 bottom
R112 "RR0510P-4020-D" resc1005n 82.2,1.2 r0 top
R113 "RR0510P-6040-D" resc1005n 82.2,2.5 r180 top
R114 "ERJ-2BQJR30X" resc1005n 39,8 r270 bottom
R115 "RR0510P-4870-D" resc1005n 41.4,4.6 r90 top
R116 "RR0510P-1541-D" resc1005n 42.3,4.6 r270 top
R117 "RR0510P-152-D" resc1005n 47.9,5 r90 bottom
R118 "RR0510P-202-D" resc1005n 47.9,2.3 r90 bottom
R119 "RR0510P-302-D" resc1005n 46.6,5 r90 bottom
R120 "RR0510P-152-D" resc1005n 46.6,2.3 r90 bottom
R122 "RR0510P-152-D" resc1005n 45.3,2.3 r90 bottom
R123 "RR0510P-4870-D" resc1005n 41.5,-4.8 r90 top
R124 "RR0510P-1541-D" resc1005n 42.8,-4.8 r270 top
R125 "ERJ-2BQJR30X" resc1005n 39.1,-1.6 r270 bottom
R126 "RR0510P-4020-D" resc1005n 82.1,6.9 r0 bottom
R127 "RR0510P-6040-D" resc1005n 82.1,5.5 r180 bottom
R128 "ERJ-2BQJR30X" resc1005n 82.2,2.5 r180 bottom
R129 "ERJ-2GEJ5R1X" resc1005n 84.9,9 r180 bottom
R130 "ERJ-2GEJ5R1X" resc1005n 36.5,4.6 r270 bottom
R131 "ERJ-2GEJ5R1X" resc1005n 36.5,-5.1 r270 bottom
R132 "ERJ-2GEJ392X" resc1005n 51.9,-11.7 r180 bottom
R133 "RR0510P-152-D" resc1005n 49.2,5 r90 bottom
R134 "RR0510P-202-D" resc1005n 49.2,2.3 r90 bottom
R135 "RR0510P-302-D" resc1005n 45.3,5 r90 bottom
R141 "ERJ-2GEJ511X" resc1005n 49.75,-4.5 r270 top
R142 "ERJ-2GEJ102X" resc1005n 44.1,-4.8 r90 top
R143 "ERJ-2GEJ392X" resc1005n 51.9,-10.4 r0 bottom
R144 "ERJ-1GNF-1002C" RESC0603 42.5,2.45 r270 top
R145 "ERJ-1GNF-1002C" resc0603 49.2,1.45 r90 top
R146 "ERJ-1GEF4023C" resc0603 51.05,3.7 r90 bottom
R147 "ERJ-1GNF1004C" resc0603 50.3,4.35 r270 bottom
R148 "ERJ-2RKF4751X" resc1005n 30.45,-4.55 r90 bottom
R201 "ERJ-2GEJ201X" resc1005n 44.75,2.1 r0 top
R202 "ERJ-2GEJ392X" resc1005n 6.4,20.1 r180 top
R203 "RR0510P-302-D" resc1005n 82.2,-8.2 r0 bottom
R204 "ERJ-2GEJ392X" resc1005n 39,-20.4 r0 top
R205 "RR0510P-302-D" resc1005n 82.2,-6.9 r0 bottom
R206 "ERJ-2GEJ392X" resc1005n 91.3,19.5 r180 top
R207 "RR0510P-302-D" resc1005n 84.3,-7.5 r90 bottom
R208 "ERJ-2GEJ392X" resc1005n 122.6,-20.4 r270 top
R209 "RR0510P-302-D" resc1005n 85.6,-7.5 r90 bottom
R210 "ERJ-2GEJ392X" resc1005n 58.9,-9.7 r90 bottom
R211 "RR0510P-302-D" resc1005n 86.9,-7.5 r90 bottom
R213 "RR0510P-302-D" resc1005n 88.2,-7.5 r90 bottom
R214 "RR0510P-122-D" resc1005n 44.5,18.4 r180 top
R215 "RR0510P-302-D" resc1005n 44.5,19.9 r0 top
R216 "RR0510P-122-D" resc1005n 8.9,-24.9 r180 top
R217 "RR0510P-302-D" resc1005n 8.9,-23.5 r0 top
R218 "RR0510P-122-D" resc1005n 120.4,24.5 r180 top
R219 "RR0510P-302-D" resc1005n 120.4,23.1 r0 top
R220 "RR0510P-122-D" resc1005n 85.1,-18.7 r0 top
R221 "RR0510P-302-D" resc1005n 85.1,-20.1 r180 top
R222 "HVC1206T5005JET" RESC3216N 127.1,3.9 r270 bottom
R223 "RR0510P-823-D" resc1005n 127.1,7.7 r270 bottom
R224 "HVC1206T5005JET" RESC3216N 119.1,3.9 r270 bottom
R225 "RR0510P-823-D" resc1005n 119.1,7.7 r270 bottom
R226 "HVC1206T5005JET" RESC3216N 99.2,0 r0 bottom
R227 "RR0510P-823-D" resc1005n 97.2,2.4 r270 bottom
R228 "RR0510P-103-D" resc1005n 90,7.1 r90 bottom
R229 "RR0510P-102-D" resc1005n 88.7,7.1 r270 bottom
R230 "ERJ-2GEJ201X" resc1005n 127.1,-5 r270 top
R231 "ERJ-2GEJ201X" resc1005n 119.1,-5 r270 top
R232 "ERJ-2GEJ201X" resc1005n 111.1,-5 r270 top
R233 "ERJ-2GEJ392X" resc1005n 6.4,18.5 r180 top
R234 "ERJ-2GEJ392X" resc1005n 39,-19 r0 top
R235 "ERJ-2GEJ392X" resc1005n 91.3,18.1 r180 top
R236 "ERJ-2GEJ392X" resc1005n 124.1,-20.4 r270 top
R237 "ERJ-2GEJ392X" resc1005n 99.3,9.5 r180 bottom
R238 "ERJ-2GEJ392X" resc1005n 68.9,4.8 r270 top
R239 "ERJ-2GEJ392X" resc1005n 31.3,10.7 r0 bottom
R240 "HVC1206T5005JET" RESC3216N 127.1,-1 r270 bottom
R241 "HVC1206T5005JET" RESC3216N 119.1,-1 r270 bottom
R242 "HVC1206T5005JET" RESC3216N 104.15,0 r0 bottom
R243 "ERJ-1GNF-1002C" RESC0603 41.65,2.45 r270 top
RT1 "NTCG063UH103HTBX" RESC0603 47.95,2.1 r270 top
RT2 "NTCG063UH103HTBX" RESC0603 84.8,0.95 r90 bottom
TP1 "1V2A" testpoint 12.5,-10.9 r180 top
TP2 "1V2B" testpoint 59.7,-7.9 r180 top
TP3 "1V2C" testpoint 73.5,12.5 r180 top
TP4 "1V2D" testpoint 102.9,-10.6 r180 top
TP5 "LV_RB" testpoint 36.8,-9.55 r180 top
TP6 "1V2_RB" testpoint 35.4,10.7 r180 top
TP7 "1V5A" testpoint 94,-7.8 r180 top
TP8 "1V5D" testpoint 92.4,-10.6 r180 top
TP9 "RX" testpoint 42.3,-2.5 r180 top
TP10 "TX" testpoint 42.25,7.25 r270 top
TP11 "1V0A" testpoint 11.5,11.6 r270 top
TP15 "I_1V5" testpoint 78.9,6.2 r270 top
TP16 "I_RX" testpoint 39.6,-7.3 r270 top
TP17 "I_TX" testpoint 39.6,2.4 r270 top

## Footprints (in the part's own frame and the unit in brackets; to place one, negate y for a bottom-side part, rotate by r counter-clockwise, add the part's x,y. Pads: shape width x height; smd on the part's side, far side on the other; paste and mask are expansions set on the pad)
BGA196C80P14X14_1200X1200X170 [mm] "BGA, 0.80mm Pitch, Square; 196 Pin, 14 Columns X 14 Rows, 12.00mm X 12.00mm X 1.70mm H"
  round 0.4 smd mask+0.051: A1(0,0) A2(0.8,0) A3(1.6,0) A4(2.4,0) A5(3.2,0) A6(4,0) A7(4.8,0) A8(5.6,0) A9(6.4,0) A10(7.2,0) A11(8,0) A12(8.8,0) A13(9.6,0) A14(10.4,0) B1(0,-0.8) B2(0.8,-0.8) B3(1.6,-0.8) B4(2.4,-0.8) B5(3.2,-0.8) B6(4,-0.8) B7(4.8,-0.8) B8(5.6,-0.8) B9(6.4,-0.8) B10(7.2,-0.8) B11(8,-0.8) B12(8.8,-0.8) B13(9.6,-0.8) B14(10.4,-0.8) C1(0,-1.6) C2(0.8,-1.6) C3(1.6,-1.6) C4(2.4,-1.6) C5(3.2,-1.6) C6(4,-1.6) C7(4.8,-1.6) C8(5.6,-1.6) C9(6.4,-1.6) C10(7.2,-1.6) C11(8,-1.6) C12(8.8,-1.6) C13(9.6,-1.6) C14(10.4,-1.6) D1(0,-2.4) D2(0.8,-2.4) D3(1.6,-2.4) D4(2.4,-2.4) D5(3.2,-2.4) D6(4,-2.4) D7(4.8,-2.4) D8(5.6,-2.4) D9(6.4,-2.4) D10(7.2,-2.4) D11(8,-2.4) D12(8.8,-2.4) D13(9.6,-2.4) D14(10.4,-2.4) E1(0,-3.2) E2(0.8,-3.2) E3(1.6,-3.2) E4(2.4,-3.2) E5(3.2,-3.2) E6(4,-3.2) E7(4.8,-3.2) E8(5.6,-3.2) E9(6.4,-3.2) E10(7.2,-3.2) E11(8,-3.2) E12(8.8,-3.2) E13(9.6,-3.2) E14(10.4,-3.2) F1(0,-4) F2(0.8,-4) F3(1.6,-4) F4(2.4,-4) F5(3.2,-4) F6(4,-4) F7(4.8,-4) F8(5.6,-4) F9(6.4,-4) F10(7.2,-4) F11(8,-4) F12(8.8,-4) F13(9.6,-4) F14(10.4,-4) G1(0,-4.8) G2(0.8,-4.8) G3(1.6,-4.8) G4(2.4,-4.8) G5(3.2,-4.8) G6(4,-4.8) G7(4.8,-4.8) G8(5.6,-4.8) G9(6.4,-4.8) G10(7.2,-4.8) G11(8,-4.8) G12(8.8,-4.8) G13(9.6,-4.8) G14(10.4,-4.8) H1(0,-5.6) H2(0.8,-5.6) H3(1.6,-5.6) H4(2.4,-5.6) H5(3.2,-5.6) H6(4,-5.6) H7(4.8,-5.6) H8(5.6,-5.6) H9(6.4,-5.6) H10(7.2,-5.6) H11(8,-5.6) H12(8.8,-5.6) H13(9.6,-5.6) H14(10.4,-5.6) J1(0,-6.4) J2(0.8,-6.4) J3(1.6,-6.4) J4(2.4,-6.4) J5(3.2,-6.4) J6(4,-6.4) J7(4.8,-6.4) J8(5.6,-6.4) J9(6.4,-6.4) J10(7.2,-6.4) J11(8,-6.4) J12(8.8,-6.4) J13(9.6,-6.4) J14(10.4,-6.4) K1(0,-7.2) K2(0.8,-7.2) K3(1.6,-7.2) K4(2.4,-7.2) K5(3.2,-7.2) K6(4,-7.2) K7(4.8,-7.2) K8(5.6,-7.2) K9(6.4,-7.2) K10(7.2,-7.2) K11(8,-7.2) K12(8.8,-7.2) K13(9.6,-7.2) K14(10.4,-7.2) L1(0,-8) L2(0.8,-8) L3(1.6,-8) L4(2.4,-8) L5(3.2,-8) L6(4,-8) L7(4.8,-8) L8(5.6,-8) L9(6.4,-8) L10(7.2,-8) L11(8,-8) L12(8.8,-8) L13(9.6,-8) L14(10.4,-8) M1(0,-8.8) M2(0.8,-8.8) M3(1.6,-8.8) M4(2.4,-8.8) M5(3.2,-8.8) M6(4,-8.8) M7(4.8,-8.8) M8(5.6,-8.8) M9(6.4,-8.8) M10(7.2,-8.8) M11(8,-8.8) M12(8.8,-8.8) M13(9.6,-8.8) M14(10.4,-8.8) N1(0,-9.6) N2(0.8,-9.6) N3(1.6,-9.6) N4(2.4,-9.6) N5(3.2,-9.6) N6(4,-9.6) N7(4.8,-9.6) N8(5.6,-9.6) N9(6.4,-9.6) N10(7.2,-9.6) N11(8,-9.6) N12(8.8,-9.6) N13(9.6,-9.6) N14(10.4,-9.6) P1(0,-10.4) P2(0.8,-10.4) P3(1.6,-10.4) P4(2.4,-10.4) P5(3.2,-10.4) P6(4,-10.4) P7(4.8,-10.4) P8(5.6,-10.4) P9(6.4,-10.4) P10(7.2,-10.4) P11(8,-10.4) P12(8.8,-10.4) P13(9.6,-10.4) P14(10.4,-10.4)
  silkscreen extent -0.8,-11.2 11.2,0.8, body extent -0.8,-11.2 11.2,0.8, height 1.7
BGA289X17 [mm]
  round 0.27 smd: A1(0,0) A2(0.5,0) A3(1,0) A4(1.5,0) A5(2,0) A6(2.5,0) A7(3,0) A8(3.5,0) A9(4,0) A10(4.5,0) A11(5,0) A12(5.5,0) A13(6,0) A14(6.5,0) A15(7,0) A16(7.5,0) A17(8,0) B1(0,-0.5) B2(0.5,-0.5) B3(1,-0.5) B4(1.5,-0.5) B5(2,-0.5) B6(2.5,-0.5) B7(3,-0.5) B8(3.5,-0.5) B9(4,-0.5) B10(4.5,-0.5) B11(5,-0.5) B12(5.5,-0.5) B13(6,-0.5) B14(6.5,-0.5) B15(7,-0.5) B16(7.5,-0.5) B17(8,-0.5) C1(0,-1) C2(0.5,-1) C3(1,-1) C4(1.5,-1) C5(2,-1) C6(2.5,-1) C7(3,-1) C8(3.5,-1) C9(4,-1) C10(4.5,-1) C11(5,-1) C12(5.5,-1) C13(6,-1) C14(6.5,-1) C15(7,-1) C16(7.5,-1) C17(8,-1) D1(0,-1.5) D2(0.5,-1.5) D3(1,-1.5) D4(1.5,-1.5) D5(2,-1.5) D6(2.5,-1.5) D7(3,-1.5) D8(3.5,-1.5) D9(4,-1.5) D10(4.5,-1.5) D11(5,-1.5) D12(5.5,-1.5) D13(6,-1.5) D14(6.5,-1.5) D15(7,-1.5) D16(7.5,-1.5) D17(8,-1.5) E1(0,-2) E2(0.5,-2) E3(1,-2) E4(1.5,-2) E5(2,-2) E6(2.5,-2) E7(3,-2) E8(3.5,-2) E9(4,-2) E10(4.5,-2) E11(5,-2) E12(5.5,-2) E13(6,-2) E14(6.5,-2) E15(7,-2) E16(7.5,-2) E17(8,-2) F1(0,-2.5) F2(0.5,-2.5) F3(1,-2.5) F4(1.5,-2.5) F5(2,-2.5) F6(2.5,-2.5) F7(3,-2.5) F8(3.5,-2.5) F9(4,-2.5) F10(4.5,-2.5) F11(5,-2.5) F12(5.5,-2.5) F13(6,-2.5) F14(6.5,-2.5) F15(7,-2.5) F16(7.5,-2.5) F17(8,-2.5) G1(0,-3) G2(0.5,-3) G3(1,-3) G4(1.5,-3) G5(2,-3) G6(2.5,-3) G7(3,-3) G8(3.5,-3) G9(4,-3) G10(4.5,-3) G11(5,-3) G12(5.5,-3) G13(6,-3) G14(6.5,-3) G15(7,-3) G16(7.5,-3) G17(8,-3) H1(0,-3.5) H2(0.5,-3.5) H3(1,-3.5) H4(1.5,-3.5) H5(2,-3.5) H6(2.5,-3.5) H7(3,-3.5) H8(3.5,-3.5) H9(4,-3.5) H10(4.5,-3.5) H11(5,-3.5) H12(5.5,-3.5) H13(6,-3.5) H14(6.5,-3.5) H15(7,-3.5) H16(7.5,-3.5) H17(8,-3.5) J1(0,-4) J2(0.5,-4) J3(1,-4) J4(1.5,-4) J5(2,-4) J6(2.5,-4) J7(3,-4) J8(3.5,-4) J9(4,-4) J10(4.5,-4) J11(5,-4) J12(5.5,-4) J13(6,-4) J14(6.5,-4) J15(7,-4) J16(7.5,-4) J17(8,-4) K1(0,-4.5) K2(0.5,-4.5) K3(1,-4.5) K4(1.5,-4.5) K5(2,-4.5) K6(2.5,-4.5) K7(3,-4.5) K8(3.5,-4.5) K9(4,-4.5) K10(4.5,-4.5) K11(5,-4.5) K12(5.5,-4.5) K13(6,-4.5) K14(6.5,-4.5) K15(7,-4.5) K16(7.5,-4.5) K17(8,-4.5) L1(0,-5) L2(0.5,-5) L3(1,-5) L4(1.5,-5) L5(2,-5) L6(2.5,-5) L7(3,-5) L8(3.5,-5) L9(4,-5) L10(4.5,-5) L11(5,-5) L12(5.5,-5) L13(6,-5) L14(6.5,-5) L15(7,-5) L16(7.5,-5) L17(8,-5) M1(0,-5.5) M2(0.5,-5.5) M3(1,-5.5) M4(1.5,-5.5) M5(2,-5.5) M6(2.5,-5.5) M7(3,-5.5) M8(3.5,-5.5) M9(4,-5.5) M10(4.5,-5.5) M11(5,-5.5) M12(5.5,-5.5) M13(6,-5.5) M14(6.5,-5.5) M15(7,-5.5) M16(7.5,-5.5) M17(8,-5.5) N1(0,-6) N2(0.5,-6) N3(1,-6) N4(1.5,-6) N5(2,-6) N6(2.5,-6) N7(3,-6) N8(3.5,-6) N9(4,-6) N10(4.5,-6) N11(5,-6) N12(5.5,-6) N13(6,-6) N14(6.5,-6) N15(7,-6) N16(7.5,-6) N17(8,-6) P1(0,-6.5) P2(0.5,-6.5) P3(1,-6.5) P4(1.5,-6.5) P5(2,-6.5) P6(2.5,-6.5) P7(3,-6.5) P8(3.5,-6.5) P9(4,-6.5) P10(4.5,-6.5) P11(5,-6.5) P12(5.5,-6.5) P13(6,-6.5) P14(6.5,-6.5) P15(7,-6.5) P16(7.5,-6.5) P17(8,-6.5) R1(0,-7) R2(0.5,-7) R3(1,-7) R4(1.5,-7) R5(2,-7) R6(2.5,-7) R7(3,-7) R8(3.5,-7) R9(4,-7) R10(4.5,-7) R11(5,-7) R12(5.5,-7) R13(6,-7) R14(6.5,-7) R15(7,-7) R16(7.5,-7) R17(8,-7) T1(0,-7.5) T2(0.5,-7.5) T3(1,-7.5) T4(1.5,-7.5) T5(2,-7.5) T6(2.5,-7.5) T7(3,-7.5) T8(3.5,-7.5) T9(4,-7.5) T10(4.5,-7.5) T11(5,-7.5) T12(5.5,-7.5) T13(6,-7.5) T14(6.5,-7.5) T15(7,-7.5) T16(7.5,-7.5) T17(8,-7.5) U1(0,-8) U2(0.5,-8) U3(1,-8) U4(1.5,-8) U5(2,-8) U6(2.5,-8) U7(3,-8) U8(3.5,-8) U9(4,-8) U10(4.5,-8) U11(5,-8) U12(5.5,-8) U13(6,-8) U14(6.5,-8) U15(7,-8) U16(7.5,-8) U17(8,-8)
  silkscreen extent -0.5,-8.5 8.5,0.5, body extent -0.5,-8.5 8.5,0.5, height 1.3
CAPC0603N [mm] "Chip Capacitor, 2-Leads, Body 0.60x0.30mm, IPC Medium Density"
  rect 0.52x0.42 smd: 1(-0.31,0) 2(0.31,0)
  body extent -0.32,-0.17 0.32,0.17, height 0.3
capc1005n [mm] "Chip Capacitor, Body 1.0x0.5mm, IPC Medium Density"
  rect 0.8x0.6 smd: 1(-0.6,0) 2(0.6,0)
  silkscreen extent -1.3,-0.2 -1.3,0.2, body extent -0.55,-0.3 0.55,0.3, height 0.6
CAPC1005N [mm] "Chip Capacitor, Body 1.0x0.5mm, IPC Medium Density"
  rect 0.8x0.6 smd: 1(-0.6,0) 2(0.6,0)
  silkscreen extent -1.3,-0.2 -1.3,0.2, body extent -0.55,-0.3 0.55,0.3, height 0.6
CAPC1608N [mm] "Chip Capacitor, Body 1.6x0.8mm, IPC Medium Density"
  rect 1x1 smd: 1(-0.8,0) 2(0.8,0)
  silkscreen extent -1.6,-0.4 -1.6,0.4, body extent -0.87,-0.48 0.87,0.48, height 0.55
capc2012n [mm] "Chip Capacitor, Body 2.0x1.3mm, IPC Medium Density"
  rect 1.3x1.5 smd: 1(-0.85,0) 2(0.85,0)
  silkscreen extent -1.8,-0.65 -1.8,0.65, body extent -1.1,-0.72 1.1,0.72, height 1.1
cnc10 [mm]
  rect 1.2x4.75 smd: 1(0,0) 2(0,5.75) 3(2.54,0) 4(2.54,5.75) 5(5.08,0) 6(5.08,5.75) 7(7.62,0) 8(7.62,5.75) 9(10.16,0) 10(10.16,5.75)
  silkscreen extent -5.1,-3.88 15.24,8.2, body extent -5.08,-2.54 15.24,8.2, height 10
cnc14 [mm]
  rect 1.2x4.75 smd: 1(0,0) 2(0,5.75) 3(2.54,0) 4(2.54,5.75) 5(5.08,0) 6(5.08,5.75) 7(7.62,0) 8(7.62,5.75) 9(10.16,0) 10(10.16,5.75) 11(12.7,0) 12(12.7,5.75) 13(15.24,0) 14(15.24,5.75)
  silkscreen extent -5.1,-3.88 20.3,8.2, body extent -5.08,-2.54 20.32,8.2, height 10
CONTACT [mm]
  rect 1.85x0.9 smd: 1(0,0)
  silkscreen extent -2,-0.6 1.2,0.6, body extent -1.92,-0.5 1.34,0.5, height 1.24
DF57-2 [mm]
  rect 0.6x0.85 smd: 1(0,0) 2(1.2,0)
  rect 0.7x0.8 smd: 3(2.35,3.775) 4(-1.15,3.775)
  silkscreen extent -1.5,-0.4 2.7,3, body extent -1.5,0 2.7,3.8, height 1.6
DF57-3 [mm]
  rect 0.6x0.85 smd: 1(0,0) 2(1.2,0) 3(2.4,0)
  rect 0.7x0.8 smd: 4(3.55,3.775) 5(-1.15,3.775)
  silkscreen extent -1.5,-0.4 3.9,3, body extent -1.5,-0.25 3.9,4, height 1.6
JMP2PCB#1 [mm]
  round 0.2 smd paste-1 mask-1: 1(0,-0.5) 2(0,0.45)
  oval 1.4x1.8 on Bottom Solder paste-1 mask-1: 9(0,0)
  Top Layer lines w0.254: -0.25,-0.45 -0.166,-0.45 ; 0.25,-0.45 0.166,-0.45 ; -0.3,0.2 cw(c0,0.2) 0.3,0.2 ; -0.25,0.45 0.25,0.45 ; -0.166,-0.45 ccw(c0,-0.2) 0,-0.5 ccw(c0,-0.2) 0.166,-0.45 ; -0.166,-0.45 cw(c0,-0.2) -0.3,-0.2 ; -0.166,-0.45 0,-0.45 0.166,-0.45 ; 0.166,-0.45 ccw(c0,-0.2) 0.3,-0.2 ; -0.3,-0.2 0.3,-0.2 ; -0.3,-0.2 -0.5,-0.2 ccw(c0,-0.2) -0.433,-0.45 ccw(c0,-0.2) 0.05,-0.697 ccw(c0,-0.2) 0.477,-0.35 ccw(c0,-0.2) 0.5,-0.2 0.3,-0.2 ; -0.5,0.2 cw(c0,0.2) 0.5,0.2 -0.5,0.2
JMP2PCB#2 [mm]
  round 0.2 smd paste-1 mask-1: 1(0,-0.5) 2(0,0.45)
  oval 1.4x1.8 on Bottom Solder paste-1 mask-1: 9(0,0)
  Top Layer lines w0.254: -0.25,-0.45 -0.166,-0.45 ; 0.25,-0.45 0.166,-0.45 ; -0.3,0.2 cw(c0,0.2) -0.166,0.45 ; 0.3,0.2 ccw(c0,0.2) 0.166,0.45 ; -0.25,0.45 -0.166,0.45 ; 0.25,0.45 0.166,0.45 ; -0.166,-0.45 ccw(c0,-0.2) 0,-0.5 ccw(c0,-0.2) 0.166,-0.45 ; -0.166,-0.45 cw(c0,-0.2) -0.3,-0.2 ; -0.166,-0.45 0,-0.45 0.166,-0.45 ; 0.166,-0.45 ccw(c0,-0.2) 0.3,-0.2 ; -0.3,-0.2 -0.5,-0.2 ccw(c0,-0.2) -0.433,-0.45 ccw(c0,-0.2) 0.05,-0.697 ccw(c0,-0.2) 0.5,-0.2 0.3,-0.2 ; -0.3,-0.2 0.3,-0.2 ; -0.166,0.45 cw(c0,0.2) 0.166,0.45 ; -0.166,0.45 0,0.45 0.166,0.45 ; -0.5,0.2 cw(c0,0.2) 0.166,0.672 cw(c0,0.2) 0.5,0.2 -0.5,0.2
LED_RED [mm] "LTST-C194KRKT"
  rect 0.8x0.8 smd: 1(0,0) 2(1.5,0)
  body extent -0.1,-0.45 1.6,0.45, height 0.6
RESC0603 [mm]
  rect 0.35x0.4 smd: 1(0,0) 2(0.65,0)
  body extent 0,-0.15 0.65,0.15, height 0.5
resc0603 [mm]
  rect 0.35x0.4 smd: 1(0,0) 2(0.65,0)
  body extent 0,-0.15 0.65,0.15, height 0.5
resc1005n [mm] "Chip Resistor, Body 1.1x0.5mm, IPC Medium Density"
  rect 0.8x0.7 smd: 1(-0.6,0) 2(0.6,0)
  body extent -0.55,-0.3 0.55,0.3, height 0.4
RESC3216N [mm] "Chip Resistor, Body 3.2x1.6mm, IPC Medium Density"
  rect 1.3x1.8 smd: 1(-1.45,0) 2(1.45,0)
  silkscreen extent -0.4,-0.8 0.4,0.8, body extent -1.68,-0.87 1.68,0.87, height 0.55
SOT-23 [mm]
  rect 0.6x1.25 smd: 1(0,0) 2(1.9,0) 3(0.95,2)
  silkscreen extent 0,0 1.9,2, body extent 0,0.3 1.9,1.7, height 1.2
testpoint [mil]
  round 40 smd paste-39.37: 1(0,0)
  silkscreen extent -39,-39 39,39
VENKEL0805 [mm]
  rect 1.1x1.2 smd: 1(0,0) 2(1.9,0)
  body extent -0.75,-0.8 2.65,0.8, height 1.7
VTRX+ [mm]
  rect 0.2x1.12 smd: 1(0,0) 2(0,2.66) 3(0.4,0) 4(0.4,2.66) 5(0.8,0) 6(0.8,2.66) 7(1.2,0) 8(1.2,2.66) 9(1.6,0) 10(1.6,2.66) 11(2,0) 12(2,2.66) 13(2.4,0) 14(2.4,2.66) 15(2.8,0) 16(2.8,2.66) 17(3.2,0) 18(3.2,2.66) 19(3.6,0) 20(3.6,2.66) 21(4,0) 22(4,2.66) 23(4.4,0) 24(4.4,2.66) 25(4.8,0) 26(4.8,2.66) 27(5.2,0) 28(5.2,2.66) 29(5.6,0) 30(5.6,2.66) 31(6,0) 32(6,2.66) 33(6.4,0) 34(6.4,2.66) 35(6.8,0) 36(6.8,2.66) 37(7.2,0) 38(7.2,2.66) 39(7.6,0) 40(7.6,2.66)
  silkscreen extent -1.2,-2.6 8.8,17.4, body extent -1.2,-2.6 8.8,17.4, height 2
WDFNX208 [mm]
  rect 0.3x0.5 smd: 1(0,0) 2(0.5,0) 3(1,0) 4(1.5,0) 5(1.5,1.8) 6(1,1.8) 7(0.5,1.8) 8(0,1.8)
  rect 1.6x0.9 smd: 9(0.75,0.9)
  silkscreen extent -0.57,-0.07 1.73,1.35, body extent -0.25,-0.12 1.75,1.87, height 0.8
WP7B-40P [mm]
  rect 0.22x0.55 smd: 1(0,0) 2(0.4,0) 3(0.8,0) 4(1.2,0) 5(1.6,0) 6(2,0) 7(2.4,0) 8(2.8,0) 9(3.2,0) 10(3.6,0) 11(4,0) 12(4.4,0) 13(4.8,0) 14(5.2,0) 15(5.6,0) 16(6,0) 17(6.4,0) 18(6.8,0) 19(7.2,0) 20(7.6,0) 21(7.6,1.85) 22(7.2,1.85) 23(6.8,1.85) 24(6.4,1.85) 25(6,1.85) 26(5.6,1.85) 27(5.2,1.85) 28(4.8,1.85) 29(4.4,1.85) 30(4,1.85) 31(3.6,1.85) 32(3.2,1.85) 33(2.8,1.85) 34(2.4,1.85) 35(2,1.85) 36(1.6,1.85) 37(1.2,1.85) 38(0.8,1.85) 39(0.4,1.85) 40(0,1.85) 41(-0.4,0) 42(8,0) 43(8,1.85) 44(-0.4,1.85)
  silkscreen extent -0.65,-1 8.25,2.3, body extent -1.5,-0.32 9.1,2.17, height 0.5

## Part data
C105 C106 C107 C108 C109 C111 C112 C113 C114 C115 C116 C117 C118 C119 C120 C121 C122 C123 C124 C125 C126 C127 C128 C129 C130 C131 C132 C133 C134 C135 C136 C138 C139 C140 C141 C150 C151 C152 C153 C154 C155 C160 C162 C163 C164 C165 C166 C167 C168 C169 C201 C202 C203 C204 C205 C206 C207 C208 C209 C210 C211 C212 C213 C214 C215 C216 C217 C218 C219 C220 C221 C222 C223 C224 C225 C226 C227 C228 C229 C230 C231 C232 C233: library part C, "CERAMIC CAPACITOR"
CT1 CT2 CT3: library part CONTACT
D1: library part LED2, "Typical RED, GREEN, YELLOW, AMBER GaAs LED"
IC1 IC4: "Low Power Gigabit Transceiver", Case=BGA289, Manufacturer=CERN
IC2: library part VTRX+_DF40C-2.0-40DS-0.4V, "VTRX+ module with 2.5mm stack Height."
IC3: library part "CERN_GBT-SCA_REV 6.2", "The Slow Control Adapter ASIC for the GBT System"
JMP1 JMP2: library part JMP2, "printed on PCB"
P1: library part "Header 5X2", "Header, 5-Pin, Dual row"
P2 P3 P11 P14 P15: library part "Header 7X2", "Header, 7-Pin, Dual row"
P4 P16 P17: library part "Header 4", "Header, 4-Pin"
P5 P6 P7 P8 P9 P10: library part WP7B-40P, "plug"
P12: library part "Header 5", "Header, 5-Pin"
Q1: library part NPN, "NPN Bipolar Transistor"
R101 R102 R103 R104 R105 R106 R107 R109 R110 R111 R112 R113 R114 R115 R116 R117 R118 R119 R120 R122 R123 R124 R125 R126 R127 R128 R129 R130 R131 R132 R133 R134 R135 R141 R142 R143 R144 R145 R146 R147 R148 R201 R202 R203 R204 R205 R206 R207 R208 R209 R210 R211 R213 R214 R215 R216 R217 R218 R219 R220 R221 R222 R223 R224 R225 R226 R227 R228 R229 R230 R231 R232 R233 R234 R235 R236 R237 R238 R239 R240 R241 R242 R243: library part R1, "FILM RESISTOR"
RT1 RT2: library part "Res Thermal", "Thermistor"
TP1 TP2 TP3 TP4 TP5 TP6 TP7 TP8 TP9 TP10 TP11 TP15 TP16 TP17: library part TP, "TEST POINT 40MIL DIA."

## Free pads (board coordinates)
  round 0.4 hole 0.25 mask+0.051: 1(11.25,0) 1(25.7,3.6) 1(25.8,-8.4) 1(26.7,-6.8) 1(27.45,0.6) 1(27.45,1.8) 1(27.5,-3) 1(27.5,-1.8) 1(27.6,-1) 1(27.6,-0.35) 1(27.6,2.8) 1(28,-1.4) 1(28.4,-7.2) 1(28.4,-3.8) 1(28.4,-3) 1(28.4,-1.8) 1(28.5,-0.6) 1(28.5,0.6) 1(28.5,1.8) 1(28.5,3) 1(29,-8.4) 1(61.875,-5.875) 1(62.875,-5.875) 1(65.6,0.9) 1(68.6,3) 1(68.9,6.9) 1(69.1,2.5) 1(69.6,-1.8) 1(70,-3.75) 1(85.1,-2.45) 1(85.15,-0.85) 1(96.4,-3.2) 1(96.4,-4.8) 1(96.4,-4) 1(96.4,-2.4) 1(96.4,-1.6) 1(96.4,-0.8) 1(96.4,0.8) 1(96.4,1.6) 1(105.531,5.569) 1(110.2,-1.3) 1(114,6.5) 1(117.9,-2.4) 1(119.1,9.2) 1(119.1,6.4) 1(125.9,-2.4) 1(127.1,9.2) 1(127.1,6.3)
  round 0.25 / inner round 0.35 / far side round 0.35 hole 0.15 mask+0.051: 1(51.35,2.9) 1(51.75,1.75) 1(51.75,-0.25) 1(52.25,-1.75) 1(52.25,-1.25) 1(52.25,-0.75) 1(52.25,0.25) 1(52.25,0.75) 1(52.25,1.25) 1(52.25,-0.25) 1(52.75,-1.75) 1(52.75,-0.75) 1(52.75,-1.25) 1(52.75,-0.25) 1(52.75,1.25) 1(52.75,2.25) 1(52.75,3.25) 1(53.25,0.25) 1(53.25,1.25) 1(53.25,-0.75) 1(53.25,-0.25) 1(53.25,0.75) 1(53.25,3.25) 1(53.25,-1.75) 1(53.25,-1.25) 1(53.25,2.25) 1(53.25,-3.25) 1(53.25,-2.75) 1(53.5,-4.4) 1(53.75,-3.75) 1(53.75,0.75) 1(53.75,1.25) 1(53.75,-2.75) 1(53.75,2.25) 1(53.75,2.75) 1(54.25,-3.25) 1(54.25,-2.75) 1(54.25,-0.25) 1(54.25,-1.75) 1(54.25,-0.75) 1(54.25,3.25) 1(54.25,0.25) 1(54.251,1.226) 1(54.275,2.25) 1(54.75,0.25) 1(54.75,0.75) 1(54.75,1.25) 1(54.75,-0.75) 1(54.75,-0.25) 1(54.775,2.25) 1(55.25,-3.25) 1(55.25,-2.75) 1(55.25,-0.75) 1(55.25,0.25) 1(55.25,0.75) 1(55.25,1.25) 1(55.25,-1.75) 1(55.25,-0.25) 1(55.25,-1.25) 1(55.75,2.75) 1(55.75,3.25) 1(55.75,-3.75) 1(55.75,-0.75) 1(55.75,0.25) 1(55.75,0.75) 1(55.75,1.25) 1(55.75,-0.25) 1(55.75,-4.25) 1(55.75,-2.75) 1(56.25,-0.25) 1(56.25,-1.75) 1(56.25,-1.25) 1(56.25,2.75) 1(56.25,-3.25) 1(56.25,-2.75) 1(56.5,-4.4) 1(56.75,2.75) 1(56.75,3.25) 1(56.75,-0.25) 1(56.75,-3.75) 1(56.75,0.75) 1(56.75,1.25) 1(56.75,-1.25) 1(57.25,0.75) 1(57.25,1.25) 1(57.25,-0.25) 1(57.25,-2.75) 1(57.25,-0.75) 1(57.25,2.75) 1(57.75,2.75) 1(57.75,3.25) 1(57.75,-3.25) 1(57.75,-2.75) 1(57.75,-0.25) 1(57.75,0.75) 1(57.75,1.25) 1(57.75,-1.75) 1(57.75,-1.25) 1(57.75,-0.75) 1(58.25,0.25) 1(58.25,0.75) 1(58.25,1.25) 1(58.25,-0.75) 1(58.25,-1.25) 1(58.25,-1.75) 1(58.25,-0.25) 1(58.25,2.75) 1(58.25,3.25) 1(58.75,-3.25) 1(58.75,-2.75) 1(58.75,-1.75) 1(58.75,2.75) 1(58.75,3.25) 1(58.75,3.75) 1(58.752,4.25) 1(59.248,-3.771) 1(59.248,3.238) 1(59.25,2.75) 1(59.25,-3.25) 1(59.25,-1.75) 1(59.25,-1.25) 1(59.25,-0.75) 1(59.25,-0.25) 1(59.25,0.25) 1(59.25,3.75) 1(59.25,4.25) 1(59.75,-3.75) 1(59.75,-3.25) 1(59.75,3.25) 1(59.75,4.25) 1(59.75,-4.25) 1(59.75,-1.75) 1(59.75,-0.25) 1(59.75,3.75) 1(60.25,-3.25) 1(60.25,4.25) 1(60.25,3.25) 1(70.6,0.5) 1(70.6,1) 1(70.75,-1.75) 1(70.75,-0.75) 1(70.75,-0.25) 1(70.75,1.75) 1(71.25,-3.75) 1(71.25,-3.25) 1(71.25,-2.75) 1(71.25,0.75) 1(71.25,-1.75) 1(71.25,-0.75) 1(71.25,-0.25) 1(71.25,1.25) 1(71.25,1.75) 1(71.75,-0.25) 1(71.75,-3.75) 1(71.75,-2.75) 1(71.75,1.25) 1(71.75,1.75) 1(71.75,-3.25) 1(71.75,-1.75) 1(71.75,-0.75) 1(72.25,-0.25) 1(72.25,-2.75) 1(72.25,-1.75) 1(72.25,-1.25) 1(72.25,-0.75) 1(72.25,0.75) 1(72.25,2.25) 1(72.75,-3.25) 1(72.75,2.25) 1(72.75,1.25) 1(72.75,1.75) 1(72.75,-3.75) 1(73.25,-4.25) 1(73.25,-0.25) 1(73.25,-3.75) 1(73.25,-0.75) 1(73.25,0.25) 1(73.25,0.75) 1(73.75,-0.75) 1(73.75,-0.25) 1(73.75,-3.25) 1(73.75,0.25) 1(73.75,0.75) 1(73.75,1.25) 1(73.75,-3.75) 1(74.25,-4.25) 1(74.25,-0.25) 1(74.25,1.25) 1(74.25,3.75) 1(74.25,4.25) 1(74.25,-0.75) 1(74.255,-3.755) 1(74.75,-0.25) 1(74.75,0.25) 1(74.75,0.75) 1(74.75,1.25) 1(74.75,3.75) 1(74.75,-2.25) 1(74.75,-0.75) 1(74.75,3.25) 1(75.25,-0.75) 1(75.25,0.75) 1(75.25,1.25) 1(75.25,4.25) 1(75.25,-1.25) 1(75.25,0.25) 1(75.25,3.75) 1(75.75,0.75) 1(75.75,1.25) 1(75.75,3.75) 1(75.75,-3.25) 1(75.75,-2.75) 1(75.75,-1.25) 1(75.75,-0.75) 1(75.75,3.25) 1(75.75,-3.75) 1(76.25,-4.25) 1(76.25,0.25) 1(76.25,0.75) 1(76.25,1.25) 1(76.25,4.25) 1(76.25,-3.75) 1(76.25,3.75) 1(76.75,0.25) 1(76.75,0.75) 1(76.75,1.25) 1(76.75,3.75) 1(76.75,-3.75) 1(76.75,-3.25) 1(76.75,-2.75) 1(76.75,-1.25) 1(76.75,-0.75) 1(76.75,-0.25) 1(76.75,3.25) 1(77.25,-4.25) 1(77.25,0.25) 1(77.25,0.75) 1(77.25,4.25) 1(77.25,-3.75) 1(77.25,-1.25) 1(77.25,-0.75) 1(77.25,-0.25) 1(77.25,1.25) 1(77.25,3.75) 1(77.75,3.75) 1(77.75,-2.75) 1(77.75,1.75) 1(77.75,3.25) 1(78.25,-2.25) 1(78.25,-1.75) 1(78.25,0.75) 1(78.25,1.25) 1(78.25,1.75) 1(78.25,-2.75) 1(78.75,-1.75) 1(78.75,-2.25) 1(78.75,-1.25) 1(78.75,0.25) 1(78.75,0.75) 1(78.75,1.25) 1(78.75,1.75) 1(78.75,-2.75) 1(79.25,-1.25) 1(79.25,0.25)
  round 0.48 hole 0.3 mask+0.051: 1(85.2,-1.6) 1(85.2,3.2) 1(86,2.4) 1(86,0.8) 1(86.8,0.8) 1(86.8,2.4) 1(87.6,-3.2) 1(87.6,-2.4) 1(87.6,-1.6) 1(87.6,-0.8) 1(87.6,0) 1(87.6,0.8) 1(87.6,-4) 1(87.6,3.2) 1(88.4,0.8) 1(88.4,1.6) 1(88.4,2.4) 1(88.4,-0.8) 1(88.4,0) 1(88.4,-2.4) 1(88.4,-1.6) 1(88.4,-4.8) 1(88.4,-4) 1(89.2,-4.8) 1(89.2,-4) 1(89.2,-3.2) 1(89.2,1.6) 1(89.2,2.4) 1(89.2,-5.6) 1(89.2,-2.4) 1(89.2,-1.6) 1(89.2,-0.8) 1(89.2,0) 1(89.2,0.8) 1(90,-4.8) 1(90,0) 1(90,0.8) 1(90,-4) 1(90,1.6) 1(90,2.4) 1(90,-5.6) 1(90.8,-2.4) 1(90.8,-5.6) 1(90.8,-4.8) 1(90.8,-4) 1(90.8,-3.2) 1(90.8,2.4) 1(90.8,-1.6) 1(90.8,-0.8) 1(91.6,-2.4) 1(91.6,-5.6) 1(91.6,-4.8) 1(91.6,-4) 1(91.6,-3.2) 1(91.6,-1.6) 1(91.6,1.6) 1(91.6,2.4) 1(91.6,0) 1(91.6,0.8) 1(92.4,0.8) 1(92.4,1.6) 1(92.4,2.4) 1(92.4,3.2) 1(92.4,-2.4) 1(92.4,-1.6) 1(92.4,-0.8) 1(92.4,0) 1(93.2,-3.2) 1(93.2,-2.4) 1(93.2,-1.6) 1(93.2,0) 1(93.2,0.8) 1(93.2,1.6) 1(93.2,2.4) 1(93.2,3.2) 1(94,-3.2) 1(94,0) 1(94,0.8) 1(94,1.6) 1(94,2.4) 1(94,3.2) 1(94,-1.6) 1(94,-0.8)

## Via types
v1: diameter 0.4, hole 0.25, Top Layer to Bottom Layer, 978 vias

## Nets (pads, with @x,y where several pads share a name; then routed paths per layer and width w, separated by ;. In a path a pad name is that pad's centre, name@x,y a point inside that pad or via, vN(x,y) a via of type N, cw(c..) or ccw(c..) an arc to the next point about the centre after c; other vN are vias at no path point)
1V0A: P5.20 P7.20 P9.20 R201.1 TP11.1 | length 175.4
  Top Layer w0.102: TP11.1@11.5,11.6 14.4,8.7 v1(17.8,8.7) ; v1(43.25,2.1) R201.1@44.15,2.1
  M1 w0.102: v1(17.8,8.7) 20.4,6.1 33.8,6.1 37.8,2.1 v1(43.25,2.1) ; v1(57.9,15.573) 57.9,15.6 113.1,15.6 113.7,15 113.7,14.3 112,12.6 107.8,12.6 v1(105.5,10.3)
  Bottom Layer w0.102: P5.20@18.2,12 18.2,9.1 v1(17.8,8.7) 15.1,8.7 14.4,9.4 14.4,13.5 18.5,17.6 55.9,17.6 57.9,15.6 57.9,9.6 58.6,8.9 61.6,8.9 61.8,9.1 P7.20@61.8,12 ; P9.20@105.4,12 105.4,10.4 v1(105.5,10.3)
1V2_mon0: C201.2 IC3.P14 P5.17 pad.1@70,-3.75 R203.2 | length 84.5
  Top Layer w0.102: C201.2@82.8,-5.6 v1(83.7,-5.6) 85.2,-5.6 IC3.P14@85.6,-5.2
  M2 w0.102: pad.1@70,-3.75 71.35,-5.1 83.2,-5.1 v1(83.7,-5.6)
  Bottom Layer w0.102: P5.17@19.4,12 19.4,9.1 19.9,8.6 34.8,8.6 36,9.8 49.4,9.8 53.6,5.6 61.8,5.6 62.9,4.5 68.5,4.5 70,3 pad.1@70,-3.75 ; R203.2@82.8,-8.2 83.3,-8.2 83.7,-7.8 v1(83.7,-5.6)
1V2_mon1: C202.2 IC3.P13 P5.18 pad.1@69.6,-1.8 R205.2 | length 82.3
  Top Layer w0.102: v1(83.7,-5) 85,-5 IC3.P13@85.6,-4.4
  M2 w0.102: pad.1@69.6,-1.8 70.75,-2.95 70.75,-3.75 71.75,-4.75 83.45,-4.75 v1(83.7,-5)
  Bottom Layer w0.102: P5.18@19,12 19,9 19.8,8.2 35,8.2 36.3,9.5 49.1,9.5 53.3,5.3 61.3,5.3 62.4,4.2 68.2,4.2 69.6,2.8 pad.1@69.6,-1.8 ; R205.2@82.8,-6.9 C202.2@82.8,-5.6 83.1,-5.6 v1(83.7,-5)
1V2_mon2: C203.2 IC3.P12 P7.17 R207.2 | length 123.2
  Top Layer w0.102: C203.2@82.8,-4.4 v1(84.1,-4.4) 84.8,-4.4 IC3.P12@85.6,-3.6
  M2 w0.102: v1(55.9,12.2) 59.9,16.2 113.5,16.2 114.6,15.1 114.6,9.2 113.6,8.2 107.3,8.2 100.3,1.2 97.6,1.2 96,-0.4 96,-2 94.4,-3.6 85.6,-3.6 84.8,-4.4 v1(84.1,-4.4)
  Bottom Layer w0.102: v1(55.9,12.2) 55.9,9.8 57.7,8 62.1,8 63,8.9 P7.17@63,12 ; v1(84.1,-4.4) 84.3,-4.6 R207.2@84.3,-6.9
1V2_mon3: C204.2 IC3.P11 P7.18 R209.2 | length 120.6
  Top Layer w0.102: v1(84.6,-3.8) IC3.P11@85.6,-2.8
  M2 w0.102: v1(56.6,12.2) 60,15.6 113.4,15.6 114,15 114,9.6 113.2,8.8 107.262,8.8 101.762,3.3 97.5,3.3 95.6,1.4 95.6,-1.6 94.4,-2.8 85.6,-2.8 v1(84.6,-3.8)
  Bottom Layer w0.102: v1(56.6,12.2) 56.6,9.7 58,8.3 62,8.3 62.6,8.9 P7.18@62.6,12 ; C204.2@82.8,-4.4 83.2,-4.4 83.8,-3.8 v1(84.6,-3.8) 84.7,-3.9 84.7,-5.5 85.6,-6.4 R209.2@85.6,-6.9
1V2_mon4: C205.2 IC3.P10 P9.17 pad.1@85.1,-2.45 R211.2 | length 40.6
  Top Layer w0.102: C205.2@82.8,-3.2 84.35,-3.2 pad.1@85.1,-2.45 85.15,-2.45 IC3.P10@85.6,-2
  M2 w0.102: pad.1@85.1,-2.45 85.15,-2.45 85.6,-2 94.4,-2 95.2,-1.2 95.2,3.6 99.619,8.019 105.681,8.019 106.6,8.938 v1(106.6,10.3)
  Bottom Layer w0.102: pad.1@85.1,-2.45 85.1,-4.6 86.9,-6.4 R211.2@86.9,-6.9 ; v1(106.6,10.3) P9.17@106.6,12
1V2_mon5: C206.2 IC3.P9 P9.18 pad.1@85.2,-1.6 R213.2 | length 41.1
  Top Layer w0.13: pad.1@85.2,-1.6 IC3.P9@85.6,-1.2
  M2 w0.102: pad.1@85.2,-1.6 85.6,-1.2 94.4,-1.2 94.8,-0.8 94.8,4 99.681,8.881 105.619,8.881 106.2,9.462 v1(106.2,9.6)
  Bottom Layer w0.102: C206.2@82.8,-3.2 83.6,-3.2 pad.1@85.2,-1.6 85.6,-2 85.6,-3.8 88.2,-6.4 R213.2@88.2,-6.9 ; v1(106.2,9.6) P9.18@106.2,12
1V2_RB: C111.1 C112.1 C113.1 C114.1 C115.1 C116.1 C117.1 C118.1 C119.1 C120.1 C121.1 C122.1 C123.1 C124.1 C125.1 C126.1 C127.1 C128.1 C129.1 C130.1 C131.1 C132.1 C133.1 C134.1 C135.1 C160.1 C162.1 C163.1 C164.1 C165.1 C166.1 C167.1 C168.1 IC1.D3 IC1.E1 IC1.E3 IC1.E4 IC1.E9 IC1.F3 IC1.F9 IC1.G3 IC1.G5 IC1.H3 IC1.J3 IC1.J5 IC1.J6 IC1.J7 IC1.J8 IC1.J9 IC1.J11 IC1.K3 IC1.K5 IC1.K6 IC1.K7 IC1.K8 IC1.K9 IC1.K11 IC1.K12 IC1.K13 IC1.L3 IC1.L10 IC1.L11 IC1.L12 IC1.L13 IC1.M3 IC1.M12 IC1.M13 IC1.N3 IC2.38 IC2.40 IC4.D3 IC4.E3 IC4.E4 IC4.F3 IC4.G3 IC4.G5 IC4.H3 IC4.J3 IC4.J5 IC4.J6 IC4.J7 IC4.J8 IC4.J9 IC4.J11 IC4.K3 IC4.K6 IC4.K7 IC4.K8 IC4.K9 IC4.K11 IC4.K12 IC4.K13 IC4.L3 IC4.L10 IC4.L11 IC4.L12 IC4.L13 IC4.M3 IC4.M12 IC4.M13 IC4.N3 IC4.T3 IC6.3 IC7.3 P1.8 P11.10 P11.11 P11.12 P11.13 P11.14 pad.1@25.7,3.6 pad.1@29,-8.4 pad.1@52.75,1.25 pad.1@52.75,2.25 pad.1@52.75,-1.25 pad.1@53.25,0.25 pad.1@53.25,1.25 pad.1@53.25,-0.25 pad.1@53.25,-0.75 pad.1@53.25,-1.25 pad.1@53.25,-1.75 pad.1@53.75,2.25 pad.1@54.25,0.25 pad.1@54.25,-0.25 pad.1@54.75,-0.25 pad.1@54.75,-0.75 pad.1@55.25,-0.25 pad.1@55.25,-0.75 pad.1@55.75,-0.25 pad.1@55.75,-0.75 pad.1@56.25,-0.25 pad.1@56.25,-1.25 pad.1@56.75,-1.25 pad.1@57.25,-0.25 pad.1@57.25,-0.75 pad.1@57.75,-0.75 pad.1@57.75,-1.25 pad.1@57.75,-1.75 pad.1@58.25,-0.25 pad.1@58.25,-0.75 pad.1@58.25,-1.25 pad.1@59.25,-1.75 pad.1@59.75,-1.75 pad.1@71.75,1.25 pad.1@71.75,1.75 pad.1@71.75,-0.25 pad.1@71.75,-3.25 pad.1@72.25,0.75 pad.1@72.25,2.25 pad.1@72.25,-0.25 pad.1@72.25,-0.75 pad.1@72.25,-1.25 pad.1@72.25,-1.75 pad.1@72.75,2.25 pad.1@73.25,-0.25 pad.1@73.75,0.25 pad.1@73.75,-0.25 pad.1@73.75,-0.75 pad.1@74.25,-0.25 pad.1@74.25,-0.75 pad.1@74.75,0.25 pad.1@74.75,-0.25 pad.1@74.75,-0.75 pad.1@75.25,-1.25 pad.1@75.75,-0.75 pad.1@75.75,-1.25 pad.1@76.25,0.25 pad.1@76.75,-0.25 pad.1@76.75,-0.75 pad.1@76.75,-1.25 pad.1@77.25,-0.25 pad.1@77.25,-0.75 pad.1@77.25,-1.25 R101.2 R102.1 R103.2 R104.2 R105.2 R106.2 R107.1 R109.2 R110.2 R202.2 R204.2 R206.2 R208.2 R210.2 R237.2 R238.2 R239.2 TP6.1 | length 113.7
  Top Layer w0.076: R204.2@39.6,-20.4 v1(40.4,-20.4) ; IC1.E1@52,2 52.25,1.75 52.75,1.75 IC1.E3@53,2 ; pad.1@52.75,2.25 IC1.D3@53,2.5 ; IC1.K5@54,-0.5 pad.1@54.25,-0.25 ; IC1.G5@54,1 54.25,0.75 pad.1@54.25,0.25 ; IC1.F9@56,1.5 56.25,1.5 ; IC1.E9@56,2 56.25,1.75 56.25,1.5 ; pad.1@56.25,-0.25 56.25,1.5 ; v1(59.6,-24.25) v1@59.7,-24.25 ; R238.2@68.9,4.2 68.9,3.6 70.25,2.25 72,2.25 ; IC4.D3@72,2.5 72,2.25 ; pad.1@72.25,2.25 72,2.25 ; IC4.J5@73,0 72.75,0.25 72.75,0.75 IC4.G5@73,1 ; 85.6,16.9 86.8,16.9 89.4,19.5 R206.2@90.7,19.5 ; v1(122.6,-21.8) R208.2@122.6,-21
  Top Layer w0.102: v1(5,20.1) R202.2@5.8,20.1 ; v1(32.6,10.7) TP6.1@35.4,10.7 ; v1(59.6,-24.25) P1.8@60.56,-24.25
  Top Layer w0.13: pad.1@52.75,-1.25 IC1.M3@53,-1.5 ; pad.1@52.75,1.25 IC1.G3@53,1 ; pad.1@52.75,2.25 IC1.E3@53,2 ; IC1.N3@53,-2 pad.1@53.25,-1.75 ; IC1.L3@53,-1 pad.1@53.25,-1.25 ; IC1.K3@53,-0.5 pad.1@53.25,-0.75 ; IC1.J3@53,0 pad.1@53.25,-0.25 ; IC1.H3@53,0.5 pad.1@53.25,0.25 ; IC1.F3@53,1.5 pad.1@53.25,1.25 ; IC1.E4@53.5,2 pad.1@53.75,2.25 ; IC1.J5@54,0 pad.1@54.25,-0.25 ; pad.1@54.25,0.25 IC1.J6@54.5,0 ; IC1.K6@54.5,-0.5 pad.1@54.75,-0.75 ; pad.1@54.75,-0.25 IC1.K7@55,-0.5 ; IC1.J7@55,0 pad.1@55.25,-0.25 ; pad.1@55.25,-0.75 IC1.K8@55.5,-0.5 ; IC1.J8@55.5,0 pad.1@55.75,-0.25 ; pad.1@55.75,-0.75 IC1.K9@56,-0.5 ; IC1.J9@56,0 pad.1@56.25,-0.25 ; pad.1@56.25,-1.25 IC1.L10@56.5,-1 ; pad.1@56.75,-1.25 IC1.L11@57,-1 ; IC1.K11@57,-0.5 pad.1@57.25,-0.75 ; IC1.J11@57,0 pad.1@57.25,-0.25 ; IC1.M12@57.5,-1.5 pad.1@57.75,-1.75 ; IC1.L12@57.5,-1 pad.1@57.75,-1.25 ; IC1.K12@57.5,-0.5 pad.1@57.75,-0.75 ; IC1.M13@58,-1.5 pad.1@58.25,-1.25 ; IC1.L13@58,-1 pad.1@58.25,-0.75 ; IC1.K13@58,-0.5 pad.1@58.25,-0.25 ; pad.1@71.75,-3.25 IC4.T3@72,-3.5 ; pad.1@71.75,-0.25 IC4.J3@72,0 ; pad.1@71.75,1.25 IC4.G3@72,1 ; pad.1@71.75,1.75 IC4.F3@72,1.5 ; IC4.N3@72,-2 pad.1@72.25,-1.75 ; IC4.M3@72,-1.5 pad.1@72.25,-1.25 ; IC4.L3@72,-1 pad.1@72.25,-0.75 ; IC4.K3@72,-0.5 pad.1@72.25,-0.25 ; IC4.H3@72,0.5 pad.1@72.25,0.75 ; IC4.E3@72,2 pad.1@72.25,2.25 ; IC4.E4@72.5,2 pad.1@72.75,2.25 ; IC4.J5@73,0 pad.1@73.25,-0.25 ; IC4.K6@73.5,-0.5 pad.1@73.75,-0.75 ; IC4.J6@73.5,0 pad.1@73.75,-0.25 ; pad.1@73.75,0.25 IC4.J7@74,0 ; IC4.K7@74,-0.5 pad.1@74.25,-0.75 ; pad.1@74.25,-0.25 IC4.J8@74.5,0 ; IC4.K8@74.5,-0.5 pad.1@74.75,-0.75 ; pad.1@74.75,-0.25 IC4.K9@75,-0.5 ; pad.1@74.75,0.25 IC4.J9@75,0 ; pad.1@75.25,-1.25 IC4.L10@75.5,-1 ; pad.1@75.75,-1.25 IC4.L11@76,-1 ; pad.1@75.75,-0.75 IC4.K11@76,-0.5 ; IC4.J11@76,0 pad.1@76.25,0.25 ; IC4.M12@76.5,-1.5 pad.1@76.75,-1.25 ; IC4.L12@76.5,-1 pad.1@76.75,-0.75 ; IC4.K12@76.5,-0.5 pad.1@76.75,-0.25 ; IC4.M13@77,-1.5 pad.1@77.25,-1.25 ; IC4.L13@77,-1 pad.1@77.25,-0.75 ; IC4.K13@77,-0.5 pad.1@77.25,-0.25
  Top Layer w0.2: IC2.38@26.67,3.4 25.9,3.4 pad.1@25.7,3.6 25.9,3.8 IC2.40@26.67,3.8 ; v1(40,-6.1) IC7.3@40,-5.5 ; v1(40,3.6) IC6.3@40,4.2
  M1 w0.102: pad.1@71.75,-3.25 72.25,-3.25 73.75,-1.75 pad.1@73.75,-0.75
  Bottom Layer w0.076: C133.1@71.56,2.25 C133.1@71.6,2.25
  Bottom Layer w0.102: R104.2@27.9,-6.1 R103.2@27.9,-8.4 pad.1@29,-8.4 30.5,-9.9 R105.2@31.2,-9.9 R106.2@32.5,-9.9 ; R239.2@31.9,10.7 v1(32.6,10.7) ; R110.2@55.7,-9.1 R109.2@57.3,-9.1 R210.2@58.9,-9.1 60.5,-9.1 61.1,-8.5 72.8,-8.5 73.5,-9.2 v1(73.5,-13.453) ; C166.1@77.8,-0.51 77.81,-0.5 79.6,-0.5 80.4,-1.3 80.4,-8.9 81,-9.5 R107.1@81.6,-9.5 ; R237.2@98.7,9.5 98.7,9.6 v1(98.7,10.3)
  Bottom Layer w0.13: v1(46.7,-3.7) R101.2@48.3,-3.7 R102.1@48.3,-2.2 ; pad.1@71.75,-0.25 pad.1@71.8,-0.2
  Bottom Layer w0.2: pad.1@53.75,2.25 pad.1@53.79,2.25 ; C113.1@59.75,-1.31 59.79,-1.31 C113.1@59.8,-1.3
  Bottom Layer w0.3: C119.1@52.56,2.75 52.56,2.44 pad.1@52.75,2.25 ; C125.1@52.71,-2.3 52.9,-2.3 53.25,-1.95 pad.1@53.25,-1.75 ; C116.1@52.75,0.81 pad.1@52.75,1.25 ; pad.1@53.25,-1.25 53.69,-1.25 C117.1@53.75,-1.19 ; pad.1@53.25,-0.25 53.75,-0.25 C126.1@53.75,-0.31 ; C114.1@54.75,-1.19 pad.1@54.75,-0.75 ; C122.1@55.75,-1.19 pad.1@55.75,-0.75 ; pad.1@56.25,-0.25 C120.1@56.25,0.44 ; C118.1@56.75,-1.79 pad.1@56.75,-1.25 ; C123.1@57.7,-2.25 C123.1@57.69,-2.25 57.75,-2.19 pad.1@57.75,-1.75 ; pad.1@58.25,-0.75 58.69,-0.75 C115.1@58.75,-0.69 ; pad.1@58.25,-0.25 58.31,-0.25 58.409,-0.151 58.416,-0.151 58.651,0.084 58.651,0.091 C124.1@58.75,0.19 ; C121.1@59.25,-2.19 pad.1@59.25,-1.75 ; pad.1@59.75,-1.75 C113.1@59.75,-1.31 ; C130.1@71.56,-1.25 pad.1@72.25,-1.25 ; C133.1@71.6,2.25 71.75,2.1 pad.1@71.75,1.75 ; pad.1@71.8,-0.2 71.96,-0.04 C164.1@71.96,0.25 ; C132.1@72.06,-2.25 72.25,-2.06 pad.1@72.25,-1.75 ; C163.1@72.75,-0.31 73.19,-0.31 pad.1@73.25,-0.25 ; pad.1@72.75,2.25 73.06,2.25 C167.1@73.25,2.06 ; pad.1@73.75,-0.75 73.81,-0.81 C168.1@73.81,-1.25 ; pad.1@74.25,-0.25 C129.1@74.25,0.19 ; C128.1@74.75,-1.19 pad.1@74.75,-0.75 ; C134.1@75.75,-1.69 pad.1@75.75,-1.25 ; pad.1@75.75,-0.75 C131.1@75.75,-0.31 ; C165.1@76.75,-1.69 pad.1@76.75,-1.25 ; pad.1@77.25,-1.25 77.3,-1.25 77.75,-1.7 C135.1@77.75,-1.69 ; pad.1@77.25,-0.75 77.56,-0.75 C166.1@77.8,-0.51
  other v1: 74.5,17.7 75.1,17.7 71.6,18.3 74.5,18.3 75.1,18.3 71.6,18.9 74.5,18.9 75.1,18.9 71.6,19.5 74.5,19.5 75.1,19.5 71.6,20.1 74.5,20.1 75.1,20.1 71.6,20.7 74.5,20.7 75.1,20.7 71.6,21.3 74.5,21.3 75.1,21.3 71.6,21.9 74.5,21.9 75.1,21.9 68.9,22.5 71.6,22.5 74.5,22.5 75.1,22.5 68.9,23.1 71.6,23.1 74.5,23.1 75.1,23.1 68.9,23.7 71.6,23.7 74.5,23.7 75.1,23.7 68.9,24.3 71.6,24.3 74.5,24.3 75.1,24.3 68.9,24.9 71.6,24.9 74.5,24.9 75.1,24.9 68.9,25.5 71.6,25.5 74.5,25.5 75.1,25.5 68.9,26.1 71.6,26.1 74.5,26.1 75.1,26.1
1V2A: C218.1 C219.1 C220.1 C221.1 P2.10 P2.11 P2.12 P2.13 P2.14 P5.1 P5.2 P5.3 P5.4 P5.5 P5.6 P5.7 P5.8 P5.9 P5.10 P6.6 P6.7 P6.8 P6.9 P6.10 R214.2 TP1.1 | length 11.6
  Top Layer w0.102: TP1.1@12.5,-10.9 12.6,-10.9 14.6,-8.9 19.7,-8.9 v1(20.4,-9.6) ; 42.2,17.2 43.3,17.2 43.9,17.8 R214.2@43.9,18.4
  other v1: 20.4,-10.8 21,-10.8 21.6,-10.8 20.4,-10.2 21,-10.2 21.6,-10.2 21,-9.6 21.6,-9.6 22.4,9.6 23,9.6 23.6,9.6 24.4,9.6 25,9.6 25.6,9.6 22.4,10.2 23,10.2 23.6,10.2 24.4,10.2 25,10.2 25.6,10.2 22.4,10.8 23,10.8 23.6,10.8 24.4,10.8 25,10.8 25.6,10.8 28,18.4 30.8,18.4 31.7,18.4 28,19 30.8,19 31.7,19 28,19.6 30.8,19.6 31.7,19.6 28,20.2 30.8,20.2 31.7,20.2 28,20.8 30.8,20.8 31.7,20.8 28,21.4 30.8,21.4 31.7,21.4 28,22 30.8,22 31.7,22 25.4,22.6 28,22.6 30.8,22.6 31.7,22.6 25.4,23.2 28,23.2 30.8,23.2 31.7,23.2 25.4,23.8 28,23.8 30.8,23.8 31.7,23.8 25.4,24.4 28,24.4 30.8,24.4 31.7,24.4 25.4,25 28,25 30.8,25 31.7,25 25.4,25.6 28,25.6 30.8,25.6 31.7,25.6 25.4,26.2 28,26.2 30.8,26.2 31.7,26.2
